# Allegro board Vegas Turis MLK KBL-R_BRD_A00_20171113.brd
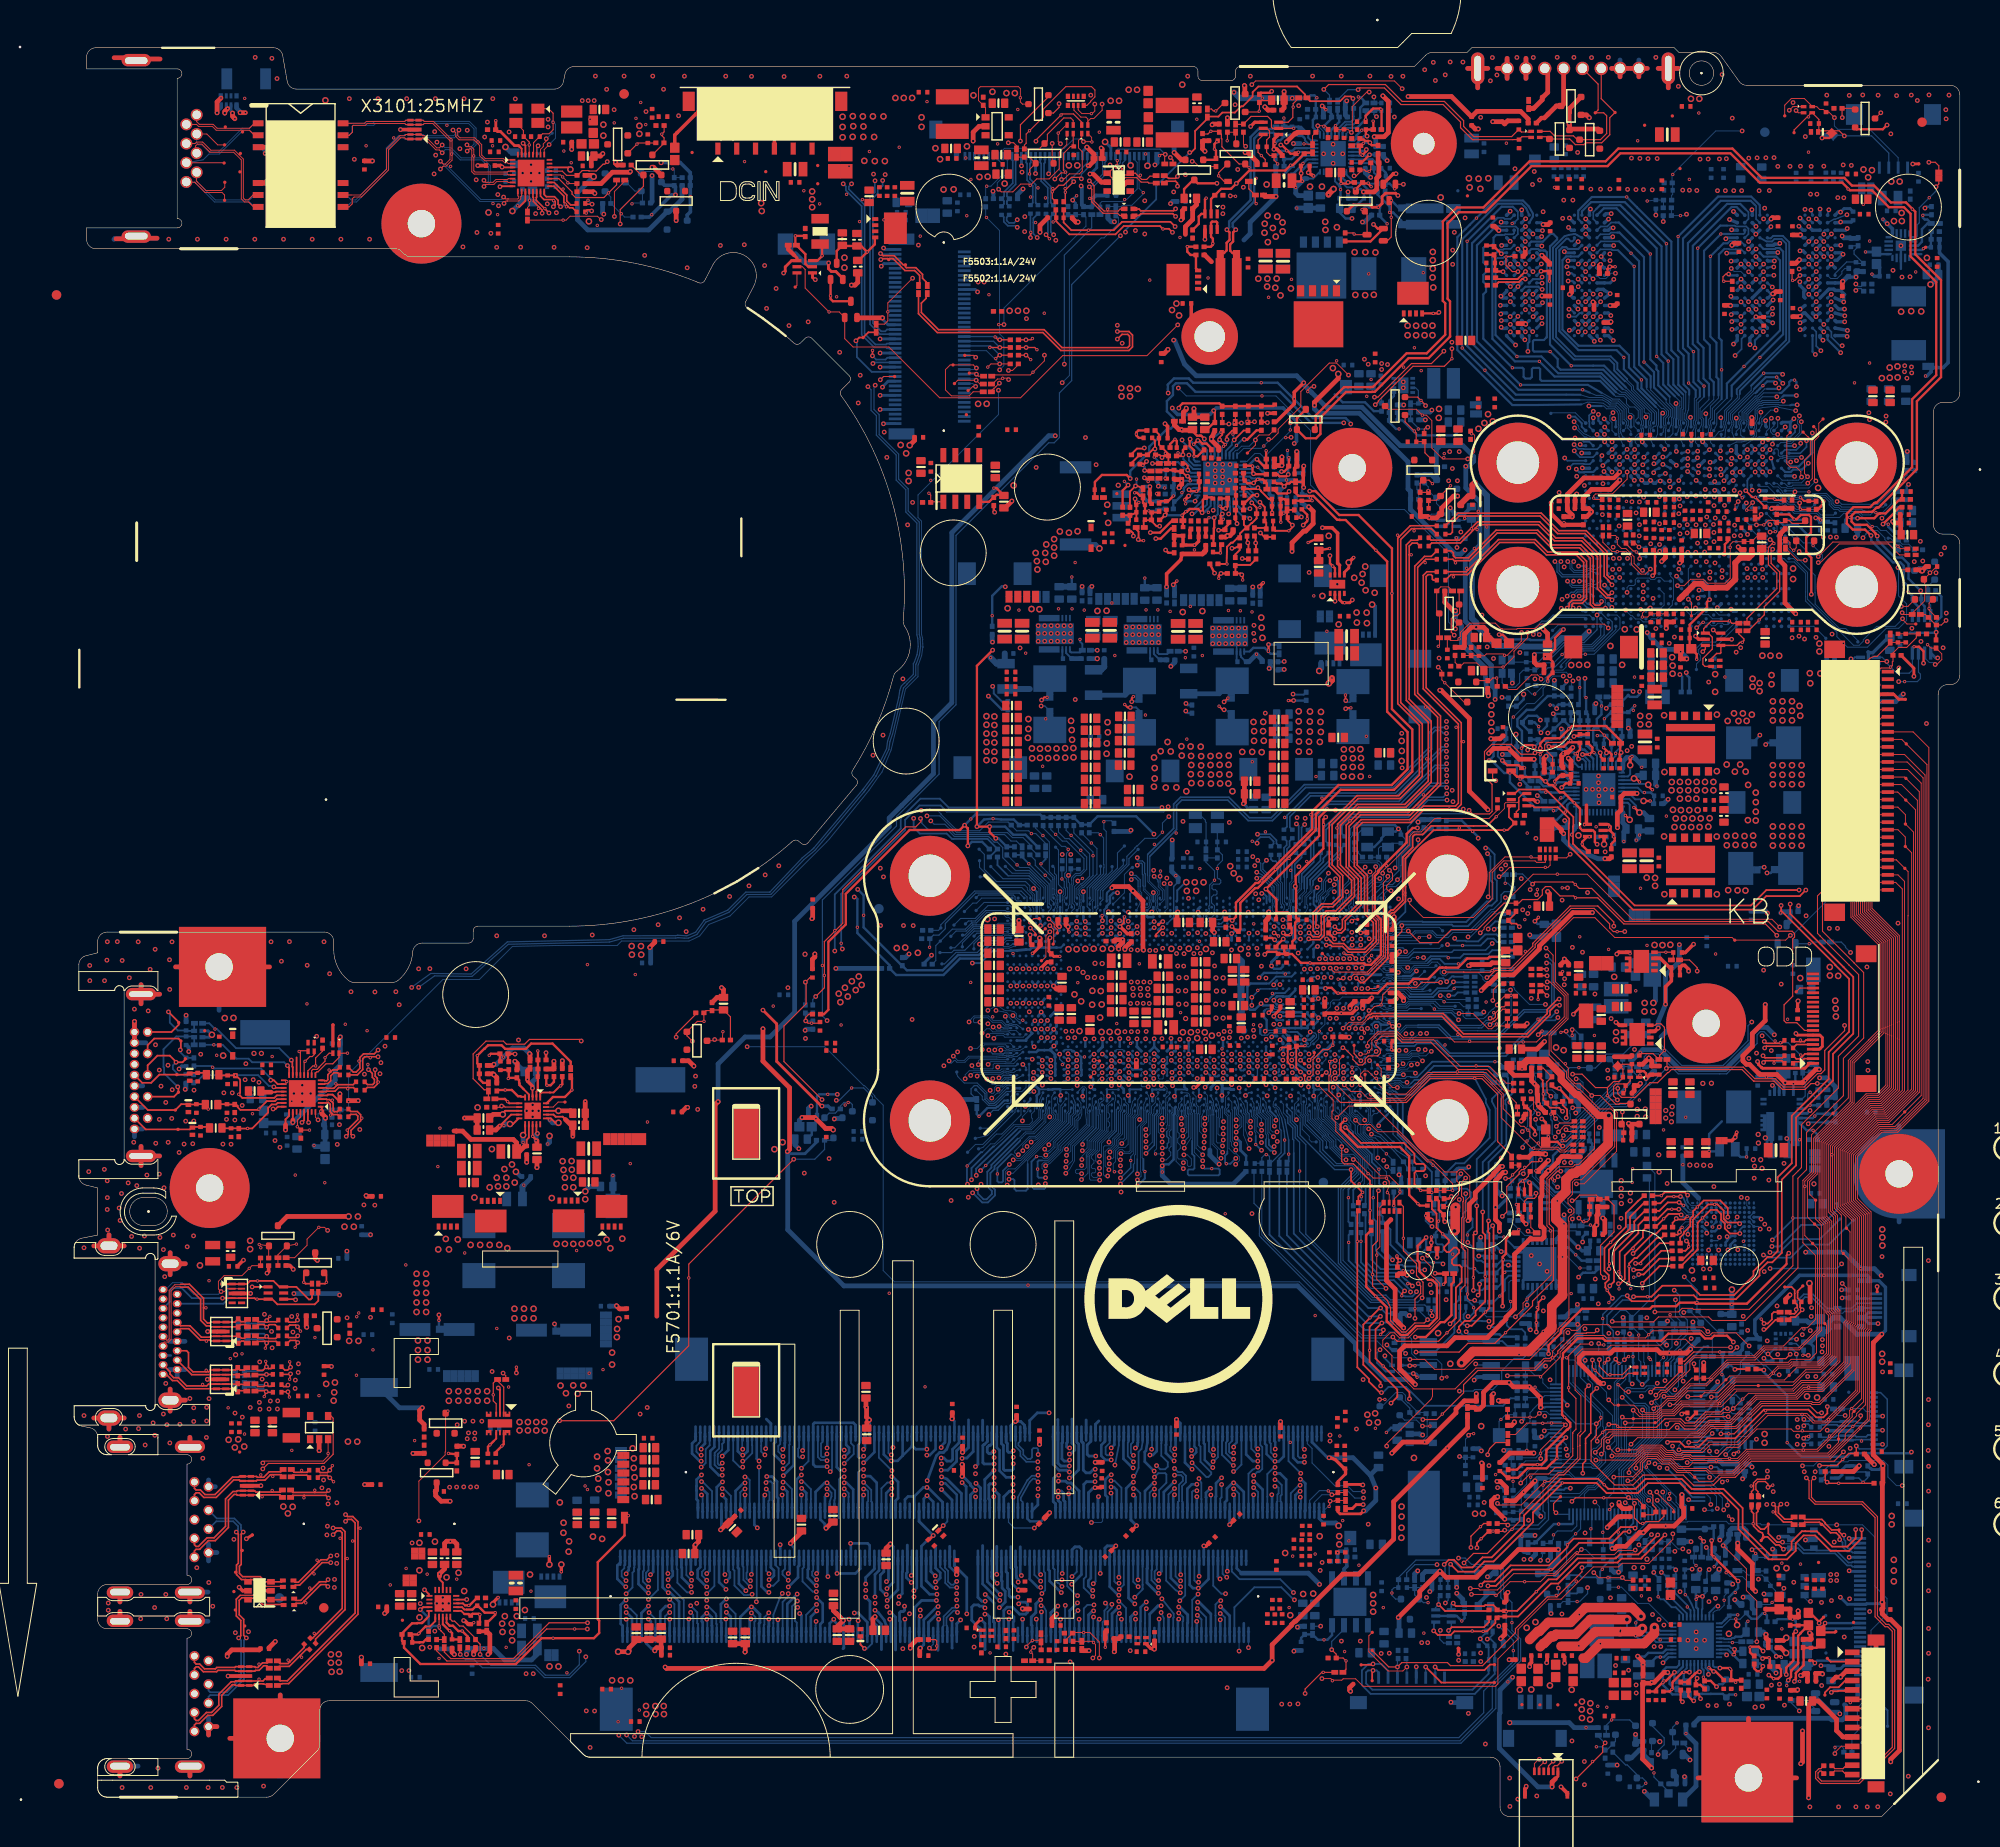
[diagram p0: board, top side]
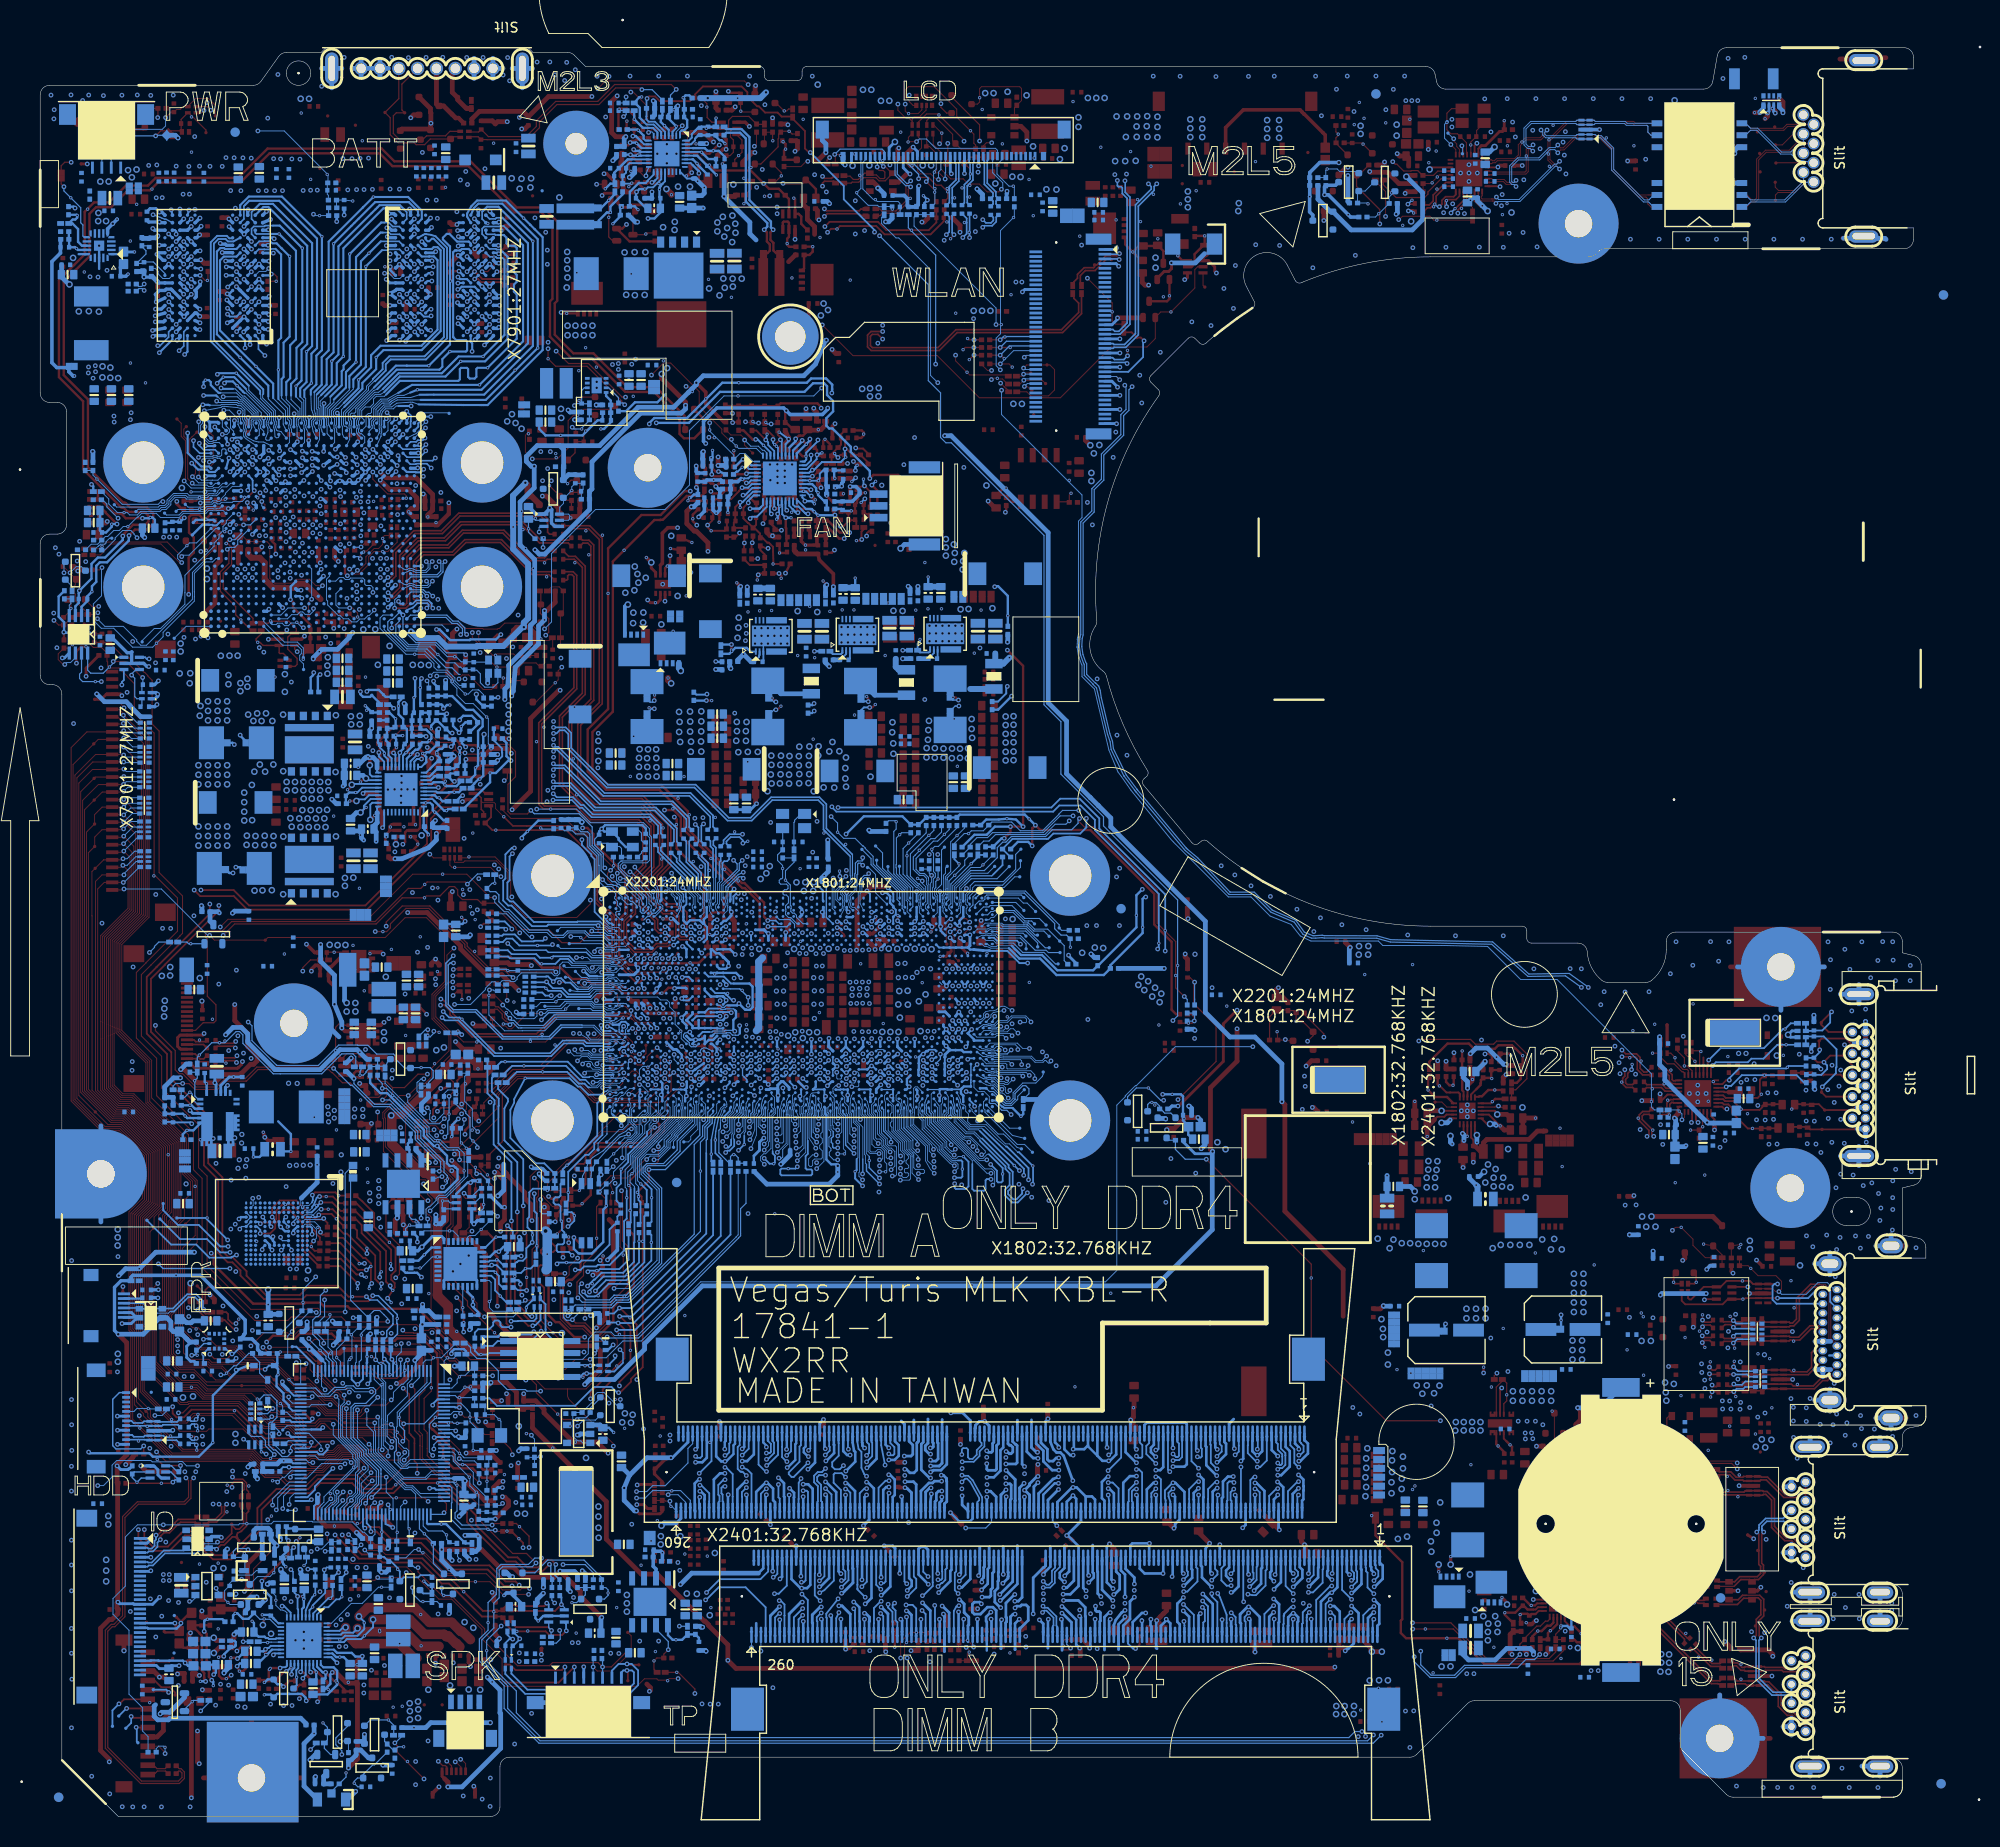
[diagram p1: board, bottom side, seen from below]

Outline 200.35 x 188 mm; copper layers: TOP, L2, L3, L4, L5GND, BOTTOM. Coordinates in mm from the lower left corner of the outline.

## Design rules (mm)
constraint set DEFAULT: min track width 0.127, pair gap 0.102
net group AUDIO_12MIL: nets CPVEE V3D3_STB
net group CL_CLK: nets CL_CLK CL_CLK_R
net group CL_DATA: nets CL_DATA CL_DATA_R
net group CL_RST#: nets CL_RST# CL_RST#_R
net group CPU_DP1_CTRL_CLK: nets CPU_DP1_CTRL_CLK DDC_CLK_HDMI
net group CPU_DP1_CTRL_DATA: nets CPU_DP1_CTRL_DATA DDC_DATA_HDMI
net group DDR4_A_ODT40-MW: nets M_A_DIMA_ODT0 M_A_DIMA_ODT1
net group DDR4_B_ODT40-MW: nets M_B_DIMB_ODT0 M_B_DIMB_ODT1
net group EDP_AUX_CPU-DIFF202: nets EDP_AUX_CPU_N EDP_AUX_CPU_P
net group EDP_TX_CON_N0: nets EDP_TX_CON_N0 EDP_TX_CPU_N0
net group EDP_TX_CON_N1: nets EDP_TX_CON_N1 EDP_TX_CPU_N1
net group EDP_TX_CON_P0: nets EDP_TX_CON_P0 EDP_TX_CPU_P0
net group EDP_TX_CON_P1: nets EDP_TX_CON_P1 EDP_TX_CPU_P1
net group EMMC_CLK: nets EMMC_CLK EMMC_CLK_R
net group EMMC_CMD: nets EMMC_CMD EMMC_CMD_R
net group EMMC_D0: nets EMMC_D0 EMMC_D0_R
net group EMMC_D1: nets EMMC_D1 EMMC_D1_R
net group EMMC_D2: nets EMMC_D2 EMMC_D2_R
net group EMMC_D3: nets EMMC_D3 EMMC_D3_R
net group EMMC_D4: nets EMMC_D4 EMMC_D4_R
net group EMMC_D5: nets EMMC_D5 EMMC_D5_R
net group EMMC_D6: nets EMMC_D6 EMMC_D6_R
net group EMMC_D7: nets EMMC_D7 EMMC_D7_R
net group EMMC_RCLK: nets EMMC_RCLK EMMC_RCLK_R
net group ESPI_CLK: nets ESPI_CLK ESPI_CLK_CPU
net group ESPI_CS#: nets ESPI_CS# ESPI_CS#_CPU
net group ESPI_IO0: nets ESPI_IO0 ESPI_IO0_CPU
net group ESPI_IO1: nets ESPI_IO1 ESPI_IO1_CPU
net group ESPI_IO2: nets ESPI_IO2 ESPI_IO2_CPU
net group ESPI_IO3: nets ESPI_IO3 ESPI_IO3_CPU
net group ESPI_RESET#: nets ESPI_RESET# ESPI_RESET#_CPU
net group FAN_TACH: nets FAN1_TACH FAN_TACH1
net group FBA_VREF: nets MVREFDA MVREFSA
net group GPU_THERMAL-DIFF220: nets GPU_DMINUS GPU_DPLUS
net group HDA_CODEC_SDIN0: nets HDA_CODEC_SDIN0 HDA_SDIN0
net group HDA_CODEC_SYNC: nets HDA_CODEC_SYNC HDA_SYNC
net group I2C0_SCL_TCH_PAD: nets I2C0_SCL_TCH_PAD I2C1_SCL_R
net group I2C0_SDA_TCH_PAD: nets I2C0_SDA_TCH_PAD I2C1_SDA_R
net group LPC-MW: nets CLKRUN#_R PWR_SECLET
net group M_A_CLK0-DIFF184: nets M_A_CLK0 M_A_CLK#0
net group M_A_CLK1-DIFF185: nets M_A_CLK1 M_A_CLK#1
net group M_A_DQS0-DIFF188: nets M_A_DQS_DN0 M_A_DQS_DP0
net group M_A_DQS1-DIFF188: nets M_A_DQS_DN1 M_A_DQS_DP1
net group M_A_DQS2-DIFF188: nets M_A_DQS_DN2 M_A_DQS_DP2
net group M_A_DQS3-DIFF188: nets M_A_DQS_DN3 M_A_DQS_DP3
net group M_A_DQS4-DIFF188: nets M_A_DQS_DN4 M_A_DQS_DP4
net group M_A_DQS5-DIFF188: nets M_A_DQS_DN5 M_A_DQS_DP5
net group M_A_DQS6-DIFF188: nets M_A_DQS_DN6 M_A_DQS_DP6
net group M_A_DQS7-DIFF188: nets M_A_DQS_DN7 M_A_DQS_DP7
net group M_B_CLK0-DIFF186: nets M_B_CLK0 M_B_CLK#0
net group M_B_CLK1-DIFF187: nets M_B_CLK1 M_B_CLK#1
net group M_B_DQS0-DIFF188: nets M_B_DQS_DN0 M_B_DQS_DP0
net group M_B_DQS1-DIFF188: nets M_B_DQS_DN1 M_B_DQS_DP1
net group M_B_DQS2-DIFF188: nets M_B_DQS_DN2 M_B_DQS_DP2
net group M_B_DQS3-DIFF188: nets M_B_DQS_DN3 M_B_DQS_DP3
net group M_B_DQS4-DIFF188: nets M_B_DQS_DN4 M_B_DQS_DP4
net group M_B_DQS5-DIFF188: nets M_B_DQS_DN5 M_B_DQS_DP5
net group M_B_DQS6-DIFF188: nets M_B_DQS_DN6 M_B_DQS_DP6
net group M_B_DQS7-DIFF188: nets M_B_DQS_DN7 M_B_DQS_DP7
net group MEM_SMBCLK: nets MEM_SMBCLK PCH_SMBCLK
net group MEM_SMBDATA: nets MEM_SMBDATA PCH_SMBDATA
net group NCT7718-DIFF1: nets NCT7718_DXN NCT7718_DXP
net group PBAT_CHG_SMBCLK: nets PBAT_CHG_SMBCLK PBAT_SMBCLK1
net group PBAT_CHG_SMBDAT: nets PBAT_CHG_SMBDAT PBAT_SMBDAT1
net group PCH_DPC_AUX-DIFF: nets PCH_DPC_AUXN PCH_DPC_AUXP
net group PCH_DPC_AUX_U-DIFF: nets PCH_DPC_AUXN_U PCH_DPC_AUXP_U
net group PCH_DPC_N0: nets PCH_DPC_N0 PCH_DPC_N0_U
net group PCH_DPC_N1: nets PCH_DPC_N1 PCH_DPC_N1_U
net group PCH_DPC_P0: nets PCH_DPC_P0 PCH_DPC_P0_U
net group PCH_DPC_P1: nets PCH_DPC_P1 PCH_DPC_P1_U
net group PCIE_CLK_XDP-DIFF1: nets PCIE_CLK_XDP_N PCIE_CLK_XDP_P
net group PCIE_RCOMP-DIFF: nets PCIE_RCOMPN PCIE_RCOMPP
net group PCIE_RX_CON_N5: nets PCIE_RX_CON_N5 PCIE_RX_CPU_N5
net group PCIE_RX_CON_P5: nets PCIE_RX_CON_P5 PCIE_RX_CPU_P5
net group PCIE_RX_CPU6-DIFF192: nets PCIE_RX_CPU_N6 PCIE_RX_CPU_P6
net group PCIE_TX_CON_N5: nets PCIE_TX_CON_N5 PCIE_TX_CPU_N5
net group PCIE_TX_CON_N6: nets PCIE_TX_CON_N6 PCIE_TX_CPU_N6
net group PCIE_TX_CON_P5: nets PCIE_TX_CON_P5 PCIE_TX_CPU_P5
net group PCIE_TX_CON_P6: nets PCIE_TX_CON_P6 PCIE_TX_CPU_P6
net group PEG_CLK_CPU1-DIFF221: nets PEG_CLK1_CPU PEG_CLK1_CPU#
net group PEG_CLK_CPU2-DIFF198: nets PEG_CLK2_CPU PEG_CLK2_CPU#
net group PEG_CLK_GPU-DIFF200: nets PEG_CLK_CPU PEG_CLK_CPU#
net group PEG_RX_CPU_N0: nets PEG_RX_CPU_N0 PEG_RX_GPU_N0
net group PEG_RX_CPU_N1: nets PEG_RX_CPU_N1 PEG_RX_GPU_N1
net group PEG_RX_CPU_N2: nets PEG_RX_CPU_N2 PEG_RX_GPU_N2
net group PEG_RX_CPU_N3: nets PEG_RX_CPU_N3 PEG_RX_GPU_N3
net group PEG_RX_CPU_P0: nets PEG_RX_CPU_P0 PEG_RX_GPU_P0
net group PEG_RX_CPU_P1: nets PEG_RX_CPU_P1 PEG_RX_GPU_P1
net group PEG_RX_CPU_P2: nets PEG_RX_CPU_P2 PEG_RX_GPU_P2
net group PEG_RX_CPU_P3: nets PEG_RX_CPU_P3 PEG_RX_GPU_P3
net group PEG_TX_CPU_N0: nets PEG_TX_CPU_N0 PEG_TX_GPU_N0
net group PEG_TX_CPU_N1: nets PEG_TX_CPU_N1 PEG_TX_GPU_N1
net group PEG_TX_CPU_N2: nets PEG_TX_CPU_N2 PEG_TX_GPU_N2
net group PEG_TX_CPU_N3: nets PEG_TX_CPU_N3 PEG_TX_GPU_N3
net group PEG_TX_CPU_P0: nets PEG_TX_CPU_P0 PEG_TX_GPU_P0
net group PEG_TX_CPU_P1: nets PEG_TX_CPU_P1 PEG_TX_GPU_P1
net group PEG_TX_CPU_P2: nets PEG_TX_CPU_P2 PEG_TX_GPU_P2
net group PEG_TX_CPU_P3: nets PEG_TX_CPU_P3 PEG_TX_GPU_P3
net group POWER_320M_POWER: nets PQ4416_1 PWR_CHG_DCIN_D
net group PWR_25_10: nets PWR_VGA_CORE_PH1 PWR_VGA_CORE_PH2
net group SATA_RX_CON_N1: nets SATA_RX_CON_N1 SATA_RX_CPU_N1
net group SATA_RX_CON_P1: nets SATA_RX_CON_P1 SATA_RX_CPU_P1
net group SATA_TX_CON_N1: nets SATA_TX_CON_N1 SATA_TX_CPU_N1
net group SATA_TX_CON_P1: nets SATA_TX_CON_P1 SATA_TX_CPU_P1
net group SENSE_CHG_AC-DIFF: nets PWR_CHG_ACN PWR_CHG_ACP
net group SENSE_CHG_PG-DIFF1: nets PG_1 PG_2
net group SENSE_CHG_SR-DIFF: nets PWR_CHG_SRN PWR_CHG_SRP
net group SIGNAL_V_F_8_OHM-MW: nets CFG3 XDP_DBRESET#
net group SIGNAL_V_F_16.5_SVID-MWS: nets VR_SVID_CLK VR_SVID_DATA
net group SPI-MW: nets SIO_RCIN# SPI_IRQ#_TPM2
net group SPI_CS_CPU_N0: nets SPI_CS_CPU_N0 SPI_CS_ROM_N0
net group SUSCLK_R: nets SUS_CLK SUSCLK_R
net group UART_2_CRXD_DTXD: nets UART_2_CRXD_DTXD UART_2_CRXD_DTXD_CON
net group UART_2_CTXD_DRXD: nets UART_2_CTXD_DRXD UART_2_CTXD_DRXD_CON
net group USB30_RX_CPU_N1: nets USB3_PRX_CTX_N1_C USB30_RX_CPU_N1
net group USB30_RX_CPU_N2: nets USB3_PRX_CTX_N2_C USB30_RX_CPU_N2
net group USB30_RX_CPU_P1: nets USB3_PRX_CTX_P1_C USB30_RX_CPU_P1
net group USB30_RX_CPU_P2: nets USB3_PRX_CTX_P2_C USB30_RX_CPU_P2
net group USB_CAMERA_PN4: nets USB_CAMERA_PN4 USB_CPU_PN4
net group USB_CAMERA_PP4: nets USB_CAMERA_PP4 USB_CPU_PP4
net group USB_CON_PN6: nets USB_CON_PN6 USB_CPU_PN6
net group USB_CON_PN7: nets USB_CON_PN7 USB_CPU_PN7
net group USB_CON_PP6: nets USB_CON_PP6 USB_CPU_PP6
net group USB_CON_PP7: nets USB_CON_PP7 USB_CPU_PP7
net group USB_CPU_PN0: nets USB_CPU_PN0 USB_PN0_C
net group USB_CPU_PN1: nets USB_CPU_PN1 USB_PN1_C
net group USB_CPU_PN2: nets USB_CPU_PN2 USB_PN2_C
net group USB_CPU_PN5: nets USB_CPU_PN5 USB_PN5_C
net group USB_CPU_PN8: nets USB_CPU_PN8 USB_PN8_C
net group USB_CPU_PP0: nets USB_CPU_PP0 USB_PP0_C
net group USB_CPU_PP1: nets USB_CPU_PP1 USB_PP1_C
net group USB_CPU_PP2: nets USB_CPU_PP2 USB_PP2_C
net group USB_CPU_PP5: nets USB_CPU_PP5 USB_PP5_C
net group USB_CPU_PP8: nets USB_CPU_PP8 USB_PP8_C
net group VCCGT_ISEN1-DIFF1: nets PWR_VCCGT_ISEN1 PWR_VCCGT_ISEN2
net group VCCGT_ISUM-DIFF1: nets PWR_VCCGT_ISUMN PWR_VCCGT_ISUMP
net group VCCGT_ISUM_GA-DIFF1: nets PWR_VCCGT_ISUMN_GA PWR_VCCGT_ISUMP_GA
net group VCCGT_ISUM_GB-DIFF1: nets PWR_VCCGT_ISUMN_GB PWR_VCCGT_ISUMP_GB
net group VCCSA_ISUM-DIFF1: nets PWR_VCCSA_ISUMN PWR_VCCSA_ISUMP
net group VCCSA_ISUM_R-DIFF1: nets PWR_VCCSA_ISUMN_R PWR_VCCSA_ISUMP_R
net group VCORE_ISUM-DIFF1: nets PWR_VCORE_ISUMN PWR_VCORE_ISUMP
net group VCORE_ISUM_G-DIFF1: nets PWR_VCORE_ISUMN_G PWR_VCORE_ISUMP_G
net group VRAM_VREFC: nets VREFC_A0 VREFC_A1
net group VRAM_WCAK0_1-DIFF1: nets WCKA0_1 WCKA0B_1
net group VRAM_WCAK1_0-DIFF1: nets WCKA1_0 WCKA1B_0
net group XDP_TCLK-MWS: nets XDP_TCK_JTAGX XDP_TCLK
net group XTAL24_IN: nets XTAL24_IN XTAL24_IN_R
net group AUDIO_BEEP_10MIL: nets AUD_HP1_JACK_L AUD_HP1_JACK_L1 AUD_HP1_JACK_R AUD_HP1_JACK_R1 AUD_PC_BEEP AUD_PC_BEEP_C AUD_PORTA_L_R_B AUD_PORTA_R_R_B AUD_SENSE AUD_SENSE_A AUD_VREF BEEP CBN CBP HDA_SPKR_R JACK_PLUG KBC_BEEP_R LINE1-L_C LINE1-L_R LINE1_L LINE1_R LINE1_VREFO LINE1_VREFO_D1 LINE1_VREFO_D2 MIC2_VREFO SPKR
net group CARD_12MIL: nets RSET
net group CFG_50-MW: nets CFG0 CFG1 CFG2 CFG4 CFG5 CFG6 CFG7 CFG8 CFG9 CFG10 CFG11 CFG12 CFG13 CFG14 CFG15 CFG16 CFG17 CFG18 CFG19
net group CLK_50-MW: nets CLKTESTA CLKTESTA_C CLKTESTB CLKTESTB_C ESPI_CLK_CON WLAN_CLKREQ_WLAN#
net group COMP_20MIL: nets CFG_RCOMP CPU_POPIRCOMP CSI2_COMP EDP_COMP EDRAM_OPIO_RCOMP EOPIO_RCOMP PCH_POPIRCOMP SD_RCOMP USBCOMP XCLK_BIASREF
net group CPU_50-MW: nets CMP_VOUT1_R H_PROCHOT# H_PROCHOT#_EC H_PROCHOT#_R PROCHOT
net group CRT_50-MW: nets CRT_B CRT_G CRT_R DP_CRT_B DP_CRT_G DP_CRT_R
net group CRT_SYNC_50-MW: nets CRT_HSYNC_CON CRT_VSYNC_CON DP_CRT_HSYNC_CON DP_CRT_VSYNC_CON
net group DDR4_A_CMD_40-MW: nets M_A_A0 M_A_A1 M_A_A2 M_A_A3 M_A_A4 M_A_A5 M_A_A6 M_A_A7 M_A_A8 M_A_A9 M_A_A10 M_A_A11 M_A_A12 M_A_A13 M_A_A14 M_A_A15 M_A_A16 M_A_ACT_N M_A_ALERT_N M_A_PARITY
net group DDR4_A_DATA_00_50-MW: nets M_A_DQ0 M_A_DQ1 M_A_DQ2 M_A_DQ3 M_A_DQ4 M_A_DQ5 M_A_DQ6 M_A_DQ7
net group DDR4_A_DATA_01_50-MW: nets M_A_DQ8 M_A_DQ9 M_A_DQ10 M_A_DQ11 M_A_DQ12 M_A_DQ13 M_A_DQ14 M_A_DQ15
net group DDR4_A_DATA_02_50-MW: nets M_A_DQ16 M_A_DQ17 M_A_DQ18 M_A_DQ19 M_A_DQ20 M_A_DQ21 M_A_DQ22 M_A_DQ23
net group DDR4_A_DATA_03_50-MW: nets M_A_DQ24 M_A_DQ25 M_A_DQ26 M_A_DQ27 M_A_DQ28 M_A_DQ29 M_A_DQ30 M_A_DQ31
net group DDR4_A_DATA_04_50-MW: nets M_A_DQ32 M_A_DQ33 M_A_DQ34 M_A_DQ35 M_A_DQ36 M_A_DQ37 M_A_DQ38 M_A_DQ39
net group DDR4_A_DATA_05_50-MW: nets M_A_DQ40 M_A_DQ41 M_A_DQ42 M_A_DQ43 M_A_DQ44 M_A_DQ45 M_A_DQ46 M_A_DQ47
net group DDR4_A_DATA_06_50-MW: nets M_A_DQ48 M_A_DQ49 M_A_DQ50 M_A_DQ51 M_A_DQ52 M_A_DQ53 M_A_DQ54 M_A_DQ55
net group DDR4_A_DATA_07_50-MW: nets M_A_DQ56 M_A_DQ57 M_A_DQ58 M_A_DQ59 M_A_DQ60 M_A_DQ61 M_A_DQ62 M_A_DQ63
net group DDR4_B_CMD_40-MW: nets M_B_A0 M_B_A1 M_B_A2 M_B_A3 M_B_A4 M_B_A5 M_B_A6 M_B_A7 M_B_A8 M_B_A9 M_B_A10 M_B_A11 M_B_A12 M_B_A13 M_B_A14 M_B_A15 M_B_A16 M_B_ACT_N M_B_ALERT_N M_B_PARITY
net group DDR4_B_DATA_00_50-MW: nets M_B_DQ0 M_B_DQ1 M_B_DQ2 M_B_DQ3 M_B_DQ4 M_B_DQ5 M_B_DQ6 M_B_DQ7
net group DDR4_B_DATA_01_50-MW: nets M_B_DQ8 M_B_DQ9 M_B_DQ10 M_B_DQ11 M_B_DQ12 M_B_DQ13 M_B_DQ14 M_B_DQ15
net group DDR4_B_DATA_02_50-MW: nets M_B_DQ16 M_B_DQ17 M_B_DQ18 M_B_DQ19 M_B_DQ20 M_B_DQ21 M_B_DQ22 M_B_DQ23
net group DDR4_B_DATA_03_50-MW: nets M_B_DQ24 M_B_DQ25 M_B_DQ26 M_B_DQ27 M_B_DQ28 M_B_DQ29 M_B_DQ30 M_B_DQ31
net group DDR4_B_DATA_04_50-MW: nets M_B_DQ32 M_B_DQ33 M_B_DQ34 M_B_DQ35 M_B_DQ36 M_B_DQ37 M_B_DQ38 M_B_DQ39
net group DDR4_B_DATA_05_50-MW: nets M_B_DQ40 M_B_DQ41 M_B_DQ42 M_B_DQ43 M_B_DQ44 M_B_DQ45 M_B_DQ46 M_B_DQ47
net group DDR4_B_DATA_06_50-MW: nets M_B_DQ48 M_B_DQ49 M_B_DQ50 M_B_DQ51 M_B_DQ52 M_B_DQ53 M_B_DQ54 M_B_DQ55
net group DDR4_B_DATA_07_50-MW: nets M_B_DQ56 M_B_DQ57 M_B_DQ58 M_B_DQ59 M_B_DQ60 M_B_DQ61 M_B_DQ62 M_B_DQ63
net group DDR4_BA_BG_40-MW: nets M_A_BA0 M_A_BA1 M_A_BG0 M_A_BG1 M_B_BA0 M_B_BA1 M_B_BG0 M_B_BG1
net group DDR4_CKE_40-MW: nets M_A_CKE0 M_A_CKE1 M_A_CS#0 M_A_CS#1 M_B_CKE0 M_B_CKE1 M_B_CS#0 M_B_CS#1
net group DDR4_RST: nets DDR4_DRAMRST#
net group DDR4_VREF_40: nets V_SM_VREF_CNTA
net group EMMC_S10: nets EMMC_E9 EMMC_E10 EMMC_F10 EMMC_K10 EMMC_RESET#
net group ERROR: nets N171297876 N171299768 N171301627 N171301632 N171301637 N171301642 N171378840 N171586817 N171586827 N171586837 N172436911
net group ESPI_50-MW: nets ESPI_ALERT# ESPI_CS#_CON ESPI_IO0_CON ESPI_IO1_CON ESPI_IO2_CON ESPI_IO3_CON ESPI_RESET#_CON
net group FFS: nets FALL_INT2 FFS_INT2 FFS_INT2_Q HDD_FALL_INT
net group GND: nets MIC_GND
net group HDA_BITCLK: nets HDA_BITCLK HDA_BITCLK_CODEC_R HDA_CODEC_BITCLK
net group HDA_CODEC_SDOUT: nets HDA_CODEC_SDOUT HDA_SDOUT HDA_SDOUT_CODEC_R
net group HDMI_CLK: nets HDMI_CLK HDMI_CLK_R HDMI_CLK_R_C
net group HDMI_CLK#: nets HDMI_CLK# HDMI_CLK#_R HDMI_CLK#_R_C
net group HDMI_DATA0: nets HDMI_DATA0 HDMI_DATA0_R HDMI_DATA0_R_C
net group HDMI_DATA0#: nets HDMI_DATA0# HDMI_DATA0#_R HDMI_DATA0#_R_C
net group HDMI_DATA1: nets HDMI_DATA1 HDMI_DATA1_R HDMI_DATA1_R_C
net group HDMI_DATA1#: nets HDMI_DATA1# HDMI_DATA1#_R HDMI_DATA1#_R_C
net group HDMI_DATA2: nets HDMI_DATA2 HDMI_DATA2_R HDMI_DATA2_R_C
net group HDMI_DATA2#: nets HDMI_DATA2# HDMI_DATA2#_R HDMI_DATA2#_R_C
net group JTAG-MW: nets PCH_JTAG_TCK PCH_JTAG_TDI PCH_JTAG_TDO PCH_JTAG_TMS
net group KBC: nets KSI0 KSI1 KSI2 KSI3 KSI4 KSI5 KSI6 KSI7 KSO0 KSO1 KSO2 KSO3 KSO4 KSO5 KSO6 KSO7 KSO8 KSO9 KSO10 KSO11 KSO12 KSO13 KSO14 KSO15 KSO16
net group LAN_MDI0N: nets MDO0-
net group LAN_MDI0P: nets MDO0+
net group LAN_MDI1N: nets MDO1-
net group LAN_MDI1P: nets MDO1+
net group LAN_MDI2N: nets MDO2-
net group LAN_MDI2P: nets MDO2+
net group LAN_MDI3N: nets MDO3-
net group LAN_MDI3P: nets MDO3+
net group LCD_BKLT: nets BKLT_CTRL EC_BRIGHTNESS EDP_BKLT_CTRL L_BKLT_CTRL LCD_BRIGHTNESS
net group LED: nets BAT1_LED# BAT2_LED# BATT_WHITE_LED# CAP_LED# CAP_LED#_S CAP_LED_R# CHG_AMBER_LED# SATA_LED#_R
net group LED_20MIL: nets BAT_AMBER BAT_WHITE CAP_LED CAP_LED_Q WHITE_LED_BAT
net group OTHER_4MIL: nets 3.3V_ALW_1 3.3V_RUN_VGA_1 3V_5V_DSW_OK A67_TP A70_TP AC_DIS AC_IN_KBC# AC_PRESENT AD_IA ATI_RST# AUX_ON AV1_TP AV71_TP B71_TP BA1_TP BB70_TP BKLT_IN_EC BLON_OUT_C BLUETOOTH_EN BLUETOOTH_EN_NGFF BOARD_ID BOARD_ID2 BOARD_ID_R BREATH_LED# CLKREQ_PCIE#1 CLKREQ_PCIE#2 CLKREQ_PCIE#3 CLKREQ_PCIE#4 CLKREQ_PCIE#5 CLKREQ_PEG#0 CMP_VIN1 CPU_DP1_HPD CPU_DP2_HPD CRT_PCH_HPD DBC_EN_R DBC_PANEL_EN DDPD_CTRLDATA DGPU_PWROK_EC DRAM_RST DRAM_RST_R DRAM_RST_VGA1 DVSS E51_RX1 E51_RX2 E51_TX1 E51_TXD_R EDP_DISP_UTIL EDP_HPD EDP_HPD_CONN FPR_SCAN# GPD2/LAN_WAKE# GPD9/SLP_WLAN# GPIO16_VGA GPIO_8_ROMSO GPIO_9_ROMSI GPIO_10_ROMSCK GPIO_17_THERMAL_INT GPIO_19_CTF GPIO_22_ROMCS# GPP_B4/CPU_GP3 GPP_B18/GSPI0_MOSI GPP_B23/SML1ALERT# GPP_C2/SMBALERT# GPP_C5/SML0ALERT# GPP_E0/SATAXPCIE0/SATAGP0 GPU_ALERT# GPU_DPRSLP GPU_DPRSLP_R H_CATERR# H_VID3 H_VID4 HDD_DEVSLP_R HDMI_HPD_B HDMI_HPD_E HOST_DEBUG_TX HOST_DEBUG_TX_CON HPD_HDMI_CON HW_ACAV_IN HW_ACAVIN_NB I_ADP ICSP_CLR ICSP_MCLR_R INT_TP# ISOLATE# JET_SVC JET_SVD JTAG_TCK_VGA JTAG_TDI_VGA JTAG_TDO_VGA JTAG_TMS_VGA JTAG_TRST#_VGA KB_LED_PWM KBC_PWRBTN# L_BKLT_EN LAN_CLKREQ_LAN# LANWAKE# LCD_TST LCD_TST_C LCD_TST_R LCDVDD_EN LED0 LED1 LED2 LID_CL_SIO# LID_CLOSE#_C MASK_SATA_LED# ME_FWP MEM_CALRP0 MESO_SVC MESO_SVD MESO_SVT MESO_U1 MESO_U3 MLPS_EN# MODEL_ID MSM# NB_MUTE# NC#AA3 NC_R NC_VSYNC P_SYS PANEL_BKEN_EC PANEL_SIZE_ID PANEL_SIZE_ID_CONN PCH_BATLOW# PCH_THERMTRIP PCH_WAKE# PDB_R PIRQA# PLL_ANALOG_IN PLT_RST#_Q_TPM2 PLT_RST_NGFF# PME# POWER_SW_IN# PQ3802_1 PRIM_PWRGD PROC_SELECT# PROJECT_ID1 PROJECT_ID2 PS_0 PS_1 PS_2 PS_3 PSID_DISABLE#_R_C PWR_5V_VCLK PWR_CHG_ACOK PWRGOOD_TEST PX_EN RESET_OUT# RTC_3P3_EN_D RTC_3P3_EN_G RTC_DET# SA0_CHA_DIM0 SA0_CHB_DIM0 SA1_CHA_DIM0 SA1_CHB_DIM0 SA2_CHA_DIM0 SA2_CHB_DIM0 SERIRQ_TPM SIO_EXT_SCI# SIO_EXT_SMI#_R SIO_EXT_WAKE# SIO_PWRBTN# SIO_SLP_A# SIO_SLP_S5# SKTOCC# SM_INTRUDER# SYSPWR_PRES TESTEN TOUCHPAD_INTR# TP_RESET TP_RS TP_WAKE_KBC# TPM_GPIO0 TPM_GPIO2 TPM_GPIO4 USB_OC1# USB_OC2# USB_POWERSHARE_VBUS_EN USB_PWR_SHR_EN_L# USB_UART_SEL_D9 VCCDSW_EN# VCCDSW_ON VCI_IN1# VCREF0 VGA_RST# VR_RDY VRAM_ID1 VSS_MECH1 VSS_MECH2 VSS_MECH3 WIFI_RF_EN WLAN_DISABLE#1 WLAN_WAKE XO_IN XO_IN2 ZVM#
net group PECI-MW: nets H_PECI_R
net group PLATFORM: nets 0D95V_VGA_EN 0D95V_VGA_EN_R 0D95V_VGA_S0_PG 1D0V_S5_PWRGD 1D8V_EN# 1D8V_EN_R# 1D8V_VGA_EN 1D8V_VGA_EN# 1D8V_VGA_EN_R# 2D5V_PWROK 3V5V_S0_ON 3V_5V_POK 3V_5V_POK# 3V_5V_POK_C ACLIM ALWON BATT_WHITE_LED_R# BLON_OUT BP_D BP_G CAMERA_DET# CAMERA_DET#_R CHG_AMBER_LED_R# EDP_VDD_EN EXT_CLK_IN_CRT EXT_PWR_GATE# FAN2_PWMVOL_LP# GPD11/LANPHYPC GPIO_5_AC_BATT GPP_B22 H_CPUPWRGD H_VCCST_PWRGD H_VCCST_PWRGD_R KBC_PWRBTN#_C LAN_ENABLE_R_C LCD_VCC_TEST_EN LCD_VCC_TEST_EN_R ME_SUS_PWR_ACK_R NB_MODE# PCH_DPWROK PCH_PLTRST# PCH_RSMRST# PCIE_CALR_RX PCIE_CALR_TX PCIE_WAKE# PD4404_A PD4404_K PLT_RST#_LAN PM_LAN_ENABLE PM_LAN_ENABLE_C PM_PCH_PWROK PM_RSMRST# PM_RSMRST#_M POL1/SPI_CEB POL2 PQ4406_2 PQ4406_3 PQ4406_5 PQ4406_6 PQ4409_C PQ4409_E PTP_DIS# PWR_1D0V_EN PWR_1D0V_PG PWR_1D8V_EN PWR_1D8V_POK PWR_1D35V_EN PWR_2D5V_POK PWR_VDDQ_PG PWR_VTT_EN Q502_G Q4009_G RSMRST_PWRGD# RTC_RST# RTCRST_ON RUNPWROK SATA_ODD_DA#_C SATA_ODD_PRSNT# SATA_ODD_PRSNT#_R SIO_SLP_S4# SLP_LAN# SLP_SUS# SM_DRAMRST# SM_PGCNTL SM_PGCNTL_R SPI_CLK_CRT SPI_SI_CRT SPI_SO_CRT SRTC_RST# SUSACK#_R TP_EN# TP_LOCK# TP_ON#_GATE TPM_SELECT TS#_DIMM0_1 TS#_DIMM1_1 USB2_ID USB2_VBUSSENSE USB_EN# USB_PWR_EN# VCCSTG_EN_R VCCSTU_EN_R
net group POWER_10M: nets 1.8V_RUN_FB 3D3V_RTC_SYS 3V5V_CT1 3V5V_CT2 +VCCAMPHYPLL_1P0 +VCCAPLL_1P0 +VCCDSW_1P0 +VCCFUSEPRG +VCCPAZIO +VCCPDSW_3P3 +VCCPRTC_3P3 +VCCST_CPU +VCCSTG +VDDQ_CPU_CLK ACOK_IN BOOST_MON FAN1_DAC_1 FAN1_PWM I_BATT LDO1_CAP LDO2_CAP LDO3_CAP MF_A0 MF_A1 MIC_CAP Q6204_G SEN_A0 SEN_A1 TPM_VDD14 TPM_VSB VCCRTCEXT VREF_CPU ZQ_A0 ZQ_A1
net group POWER_10M_POWER: nets 3V_FEEDBACK AC_DIS_R AC_IN#_G AD+_G_1 AD+_G_2 AD+_R AD_OFF_L AD_OFF_R CCLIM DC_IN_D DPLL_PVDD DPLL_VDDC EN/DEM_VGA MPV18 PQ3809_D PQ8206_3 PR_2 PWR_OPCN PWR_OPCP PWR_VBAT SPV10 SPV18 TOPAZ_OCP VGA_SVC VGA_SVD VGA_SVT VGA_VDD_RUN_FB_H VGA_VDD_RUN_FB_L VGA_VSUM-_1 VSS_AY71
net group POWER_15M: nets 3D3V_TP_S5_R PS_ID PS_ID_R PS_ID_R1 Q6205_Q
net group POWER_20M: nets 1D8V_S0 1D8V_S5_KBC 3D3V_AUX_KBC_R 3D3V_AUX_S5 +3V_1D8V_AVDD +RTC_CELL_VBAT +RTC_VCC +V_VREF_PATH1 CCG4_I2C_INT# EMMC_VDDI MCT0 MCT1 MCT2 MCT3 PBAT_PRES1# PBAT_PRES# RTC_3D3V RTC_AUX_S5 SYS_PRES1#
net group POWER_20M_POWER: nets 3D3V_PWR_2 5V_PWR_2 AVCC33 CPVDD
net group POWER_40M: nets 3D3V_S5_PCH_GEN9
net group POWER_40M_POWER: nets PWR_VDDQ_VTTREF
net group POWER_120MIL: nets PWR_VCORE_VIN PWR_VDDQ_VDDQ PWR_VGA_CORE_VDDIO
net group POWER_2680M_POWER: nets U22_POWER_K52
net group PWR_10_10: nets PWR_1D0V_PFM PWR_1D0V_SS PWR_1D0V_TON PWR_1V35V_ILMT PWR_2D5V_EN PWR_3D3V_CS2 PWR_3D3V_EN2 PWR_5V_CS1 PWR_5V_EN1 PWR_5V_EN1_R PWR_CHG_ACDET PWR_CHG_AMON PWR_CHG_BATGONE PWR_CHG_BMON PWR_CHG_CMSRC PWR_CHG_COMP PWR_CHG_DCIN PWR_CHG_DCIN_R PWR_CHG_FSET PWR_CHG_NTC PWR_CHG_NTC_1 PWR_CHG_PROG PWR_CHG_REGN PWR_CHG_SCL PWR_CHG_SDA PWR_CHG_SRN_R PWR_CHG_SRP_R PWR_VCCGT_COMP PWR_VCCGT_COMP1 PWR_VCCGT_FCCM# PWR_VCCGT_FCCM#_RA PWR_VCCGT_FCCM#_RB PWR_VCCGT_IMON PWR_VCCGT_ISUMN_P_1 PWR_VCCGT_ISUMN_P_2 PWR_VCCGT_ISUMN_RC PWR_VCCGT_ISUMNB PWR_VCCGT_NTC PWR_VCCGT_NTC1 PWR_VCCGT_RTN PWR_VCCSA_COMP PWR_VCCSA_COMP_RC PWR_VCCSA_FCCM PWR_VCCSA_IMON PWR_VCCSA_ISUMN_P_1 PWR_VCCSA_ISUMN_P_2 PWR_VCCSA_ISUMN_RC PWR_VCCSA_ISUMNB PWR_VCCSA_RTN PWR_VCORE_COMP PWR_VCORE_COMP1 PWR_VCORE_FCCM# PWR_VCORE_FCCM#_R PWR_VCORE_IMON PWR_VCORE_ISUMN_P_1 PWR_VCORE_ISUMN_P_2 PWR_VCORE_ISUMN_RC PWR_VCORE_ISUMNA PWR_VCORE_NTC PWR_VCORE_NTC1 PWR_VCORE_PROG1 PWR_VCORE_PROG2 PWR_VCORE_RTN PWR_VCORE_VRHOT# PWR_VDDQ_CS PWR_VDDQ_EN PWR_VDDQ_TON PWR_VDDQ_VID PWR_VGA_CORE_COMP PWR_VGA_CORE_COMP_1 PWR_VGA_CORE_EN_R# PWR_VGA_CORE_ENABLE PWR_VGA_CORE_IMON_NB PWR_VGA_CORE_ISEN1 PWR_VGA_CORE_ISEN2 PWR_VGA_CORE_ISUMN PWR_VGA_CORE_ISUMP PWR_VGA_CORE_NTC PWR_VGA_CORE_NTC_NB PWR_VGA_CORE_PGOOD PWR_VGA_CORE_PWROK PWR_VGA_CORE_RTN PWR_VGA_CORE_SVC PWR_VGA_CORE_SVD PWR_VGA_CORE_SVT PWR_VGA_CORE_VO1 PWR_VGA_CORE_VO2 PWR_VGA_CORE_VR_HOT# PWR_VGA_CORE_VSEN PWR_VGA_CORE_VSUM-
net group PWR_15_20: nets PWR_0D95V_FB PWR_1D0V_VFB PWR_1D0V_VFB_A PWR_1D35V_FB PWR_1D35V_FB_A PWR_2D5V_FB PWR_3D3V_FB2 PWR_3D3V_FB2_R PWR_5V_FB1 PWR_5V_FB1_R PWR_CHG_ASGATE PWR_VCCGT_FB PWR_VCCGT_FB1 PWR_VCCGT_FB2 PWR_VCCGT_FB_RC PWR_VCCSA_FB PWR_VCCSA_FB_RC PWR_VCORE_FB1 PWR_VCORE_FB2 PWR_VCORE_FB_RC PWR_VDDQ_FB PWR_VGA_CORE_FB PWR_VGA_CORE_FB2_R PWR_VGA_CORE_FB_R
net group PWR_20_10: nets PWR_5V_VO1 PWR_VCCGT_VCCDA PWR_VCCGT_VCCDB PWR_VCORE_VCC PWR_VCORE_VCC_R PWR_VDDQ_VDD PWR_VGA_CORE_IMON PWR_VGA_CORE_VDD VDD
net group PWR_25_30: nets PWR_1D0V_BT PWR_1D0V_SNUB PWR_1D35V_BOOT PWR_1D35V_BOOT_A PWR_3D3V_SNUB PWR_3D3V_VBST2 PWR_3D3V_VBST2_1 PWR_5V_SNUB PWR_5V_VBST1 PWR_5V_VBST1_1 PWR_CHG_BTST PWR_CHG_BTST1 PWR_VCCGT_BOOTA_RC PWR_VCCGT_BOOTB_RC PWR_VCCGT_PWMA PWR_VCCGT_PWMB PWR_VCCGT_SNB2 PWR_VCCSA_BST_RC PWR_VCCSA_DRVL PWR_VCCSA_PWM PWR_VCORE_BOOT_RC PWR_VCORE_PWM PWR_VCORE_SNB PWR_VDDQ_BOOT PWR_VDDQ_BOOT_A PWR_VGA_CORE__BOOT1_1 PWR_VGA_CORE__BOOT2_1 PWR_VGA_CORE_BOOT1 PWR_VGA_CORE_BOOT2
net group REF10M: nets VR_CAP
net group SATA_RX_CON_N0: nets SATA_RX_CPU_N0
net group SATA_RX_CON_P0: nets SATA_RX_CPU_P0
net group SATA_TX_CON_N0: nets SATA_TX_CPU_N0
net group SATA_TX_CON_P0: nets SATA_TX_CPU_P0
net group SENSE: nets VCC_SENSE VCCGT_SENSE VCCSA_SENSE VSS_SENSE VSSGT_SENSE VSSSA_SENSE
net group SIGNAL_V_F_4MIL: nets HDD_DEVSLP ITP_PMODE KB_DET# PLT_RST# USB_OC0# USB_OC3# VR_EN
net group SIGNAL_V_F_5MIL: nets 3V_5V_EN ALL_SYS_PWRGD DGPU_HOLD_RST# DGPU_PWR_EN DGPU_PWR_EN_R DGPU_PWROK DGPU_PWROK_R SIO_SLP_S0# SIO_SLP_S3# SYS_PWROK TOUCH_PANEL_INTR#
net group SIGNAL_V_F_14_OHM-MW: nets VR_SVID_ALERT#
net group SIGNAL_V_F_15_OHM-MW: nets H_PECI
net group SM_RCOMP: nets SM_RCOMP_0 SM_RCOMP_1 SM_RCOMP_2
net group SMB_CLK_THM_R: nets SMB_CLK_THM_R SMB_CLK_VGA SMB_CLK_VGA_R SML1_SMBCLK
net group SMB_DATA_THM_R: nets SMB_DATA_THM_R SMB_DATA_VGA SMB_DATA_VGA_R SML1_SMBDATA
net group SMBUS_50-MWS: nets CLK_TP_SIO CPU_DP2_CTRL_CLK CPU_DP2_CTRL_DATA CRT_DDCCLK_CON CRT_DDCCLK_CON_R CRT_DDCDATA_CON CRT_DDCDATA_CON_R DAT_TP_SIO DDC_CLK_PH1 DDC_DATA_PH2 DMIC_CLK DMIC_CLK_EDP DMIC_CLK_R DMIC_DATA DMIC_DATA_EDP DMIC_DATA_R GPU_THM_SMBCLK GPU_THM_SMBDAT I2C0_SCL I2C0_SDA I2C1_SCL I2C1_SDA ICSP_CLK ICSP_CLK_R ICSP_DAT ICSP_DATA_R SML0_SMBCLK SML0_SMBDATA TPCLK_C TPDATA_C
net group SPI_CLK_CPU: nets SPI_CLK_CPU SPI_CLK_ROM SPI_CLK_ROM_R SPI_CLK_ROM_TPM2
net group SPI_CS2#_R_TPM2: nets SPI_CS2#_R_TPM2 SPI_CS_CPU_N2 SPI_CS_ROM_N2
net group SPI_HOLD_CPU: nets SPI_HOLD_CPU SPI_HOLD_ROM SPI_HOLD_ROM_R
net group SPI_SI_CPU: nets SPI_SI_CPU SPI_SI_ROM SPI_SI_ROM_R SPI_SI_ROM_TPM2
net group SPI_SO_CPU: nets SPI_SO_CPU SPI_SO_ROM SPI_SO_ROM_R SPI_SO_ROM_TPM2
net group SPI_WP_CPU: nets SPI_WP_CPU SPI_WP_ROM SPI_WP_ROM_R
net group SVID-MW: nets H_CPU_SVIDALRT# H_CPU_SVIDCLK H_CPU_SVIDDAT PWR_VCORE_ALERT# PWR_VCORE_SCLK PWR_VCORE_SDIO
net group T8-MW: nets CMP_VIN0 CMP_VIN0_R CMP_VOUT0 VD_IN1_C
net group TESTPD_4MIL: nets CPU_A16_TP CPU_D3_TP CPU_D4_TP CPU_D5_TP CPU_D6_TP RSVD_F65 RSVD_G65 RSVD_TP_AW70 RSVD_TP_AW71 RSVD_TP_BA68 RSVD_TP_BA70 TP1_AY4 TP2_BB3
net group THERM_10M-MS: nets FON#
net group THERM_SHUTDOWN: nets GPU_PWR_LEVEL GPU_PWR_LEVEL_R GPU_T_CRIT# GPU_T_CRIT_R# PURE_HW_SHUTDOWN# THERM_SYS_SHDN#
net group UART_MW-MW: nets LPSS_UART2_CTS# UART0_CTS# UART0_RTS# UART0_TXD UART1_CTS# UART1_RXD
net group USB30_TX_CPU_N1: nets USB3_PTX_CRX_N1_C USB3_PTX_CRX_N1_R USB30_TX_CPU_N1
net group USB30_TX_CPU_N2: nets USB3_PTX_CRX_N2_C USB3_PTX_CRX_N2_R USB30_TX_CPU_N2
net group USB30_TX_CPU_P1: nets USB3_PTX_CRX_P1_C USB3_PTX_CRX_P1_R USB30_TX_CPU_P1
net group USB30_TX_CPU_P2: nets USB3_PTX_CRX_P2_C USB3_PTX_CRX_P2_R USB30_TX_CPU_P2
net group VRAM_DBI: nets DDBIA0_2 DDBIA0_3 DDBIA1_0
net group VRAM_DQA-MWS: nets DQA0_16 DQA0_17 DQA0_18 DQA0_19 DQA0_20 DQA0_21 DQA0_22 DQA0_23 DQA0_24 DQA0_25 DQA0_26 DQA0_27 DQA0_28 DQA0_29 DQA0_30 DQA0_31 DQA1_0 DQA1_1 DQA1_2 DQA1_3 DQA1_4 DQA1_5 DQA1_6 DQA1_7
net group VRAM_EDC: nets EDCA0_2 EDCA0_3 EDCA1_0
net group XDP-MW: nets XDP_PRDY# XDP_PREQ# XDP_TDI XDP_TDO_CPU XDP_TMS XDP_TRST#
net group XDP_BPM-MW: nets XDP_BPM0 XDP_BPM1 XDP_BPM2 XDP_BPM3
net group XTAL24_IN_U42: nets XTAL24_IN_U42
net group XTAL24_OUT_R_U42: nets XTAL24_OUT_U42
net group XTAL-MW: nets LANXIN LANXOUT MEC_XTAL1_R MEC_XTAL2 RTC_X1 RTC_X2 XTAL24_OUT XTAL_KBC_2 XTL_27M_X1_VGA XTL_27M_X2_VGA

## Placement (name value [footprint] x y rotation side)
AFTP2501  AFTE14P-GP  [AFTE14P-75]  34.88 20.86 0 top
AFTP2502  AFTE14P-GP  [AFTE14P-75]  36.71 42.57 0 top
AFTP2601  AFTE14P-GP  [AFTE14P-75]  110.79 140.6 0 top
AFTP2602  AFTE14P-GP  [AFTE14P-75]  109.52 138.5 0 top
AFTP2603  AFTE14P-GP  [AFTE14P-75]  111.65 135.1 0 top
AFTP2901  AFTE14P-GP  [AFTE14P-75]  153.82 11.89 0 top
AFTP2902  AFTE14P-GP  [AFTE14P-75]  155.73 11.86 0 top
AFTP2903  AFTE14P-GP  [AFTE14P-75]  157.64 11.86 0 top
AFTP2904  AFTE14P-GP  [AFTE14P-75]  159.54 11.86 0 top
AFTP3201  AFTE14P-GP  [AFTE14P-75]  16.01 173.7 0 top
AFTP3202  AFTE14P-GP  [AFTE14P-75]  15.93 175.74 0 top
AFTP3203  AFTE14P-GP  [AFTE14P-75]  17.66 176.76 0 top
AFTP3204  AFTE14P-GP  [AFTE14P-75]  15.98 171.78 0 top
AFTP3205  AFTE14P-GP  [AFTE14P-75]  17.61 174.8 0 top
AFTP3206  AFTE14P-GP  [AFTE14P-75]  16.06 179.58 0 top
AFTP3207  AFTE14P-GP  [AFTE14P-75]  17.89 179.05 0 top
AFTP3208  AFTE14P-GP  [AFTE14P-75]  15.98 177.68 0 top
AFTP3601  AFTE14P-GP  [AFTE14P-75]  17.58 38.74 270 top
AFTP3602  AFTE14P-GP  [AFTE14P-75]  17.86 28.27 270 top
AFTP3603  AFTE14P-GP  [AFTE14P-75]  17.15 25.96 270 top
AFTP3604  AFTE14P-GP  [AFTE14P-75]  18.93 29.92 0 top
AFTP3605  AFTE14P-GP  [AFTE14P-75]  17.97 17.68 270 top
AFTP3606  AFTE14P-GP  [AFTE14P-75]  17.13 21.95 0 top
AFTP3607  AFTE14P-GP  [AFTE14P-75]  18.12 20.25 0 top
AFTP3608  AFTE14P-GP  [AFTE14P-75]  16.97 23.9 0 top
AFTP4301  AFTE14P-GP  [AFTE14P-75]  79 173.54 0 top
AFTP4302  AFTE14P-GP  [AFTE14P-75]  166.86 179.76 0 top
AFTP4303  AFTE14P-GP  [AFTE14P-75]  156.61 180.94 0 top
AFTP4304  AFTE14P-GP  [AFTE14P-75]  163.72 181.12 0 top
AFTP4305  AFTE14P-GP  [AFTE14P-75]  155.98 182.74 0 top
AFTP4306  AFTE14P-GP  [AFTE14P-75]  148.04 172.25 0 top
AFTP4307  AFTE14P-GP  [AFTE14P-75]  147.02 172.79 180 bottom
AFTP4308  AFTE14P-GP  [AFTE14P-75]  161.62 181.08 0 top
AFTP4309  AFTE14P-GP  [AFTE14P-75]  170.62 175.15 0 top
AFTP4310  AFTE14P-GP  [AFTE14P-75]  169.81 180.75 0 top
AFTP4311  AFTE14P-GP  [AFTE14P-75]  151.99 179.9 0 top
AFTP4312  AFTE14P-GP  [AFTE14P-75]  64.07 178.97 0 top
AFTP4313  AFTE14P-GP  [AFTE14P-75]  73.48 174.82 0 top
AFTP4314  AFTE14P-GP  [AFTE14P-75]  65.66 176.86 0 top
AFTP4315  AFTE14P-GP  [AFTE14P-75]  79 175.48 0 top
AFTP4601  AFTE14P-GP  [AFTE14P-75]  124.66 144.91 0 top
AFTP5602  AFTE14P-GP  [AFTE14P-75]  11.34 82.43 270 top
AFTP5603  AFTE14P-GP  [AFTE14P-75]  11.83 80.54 270 top
AFTP5604  AFTE14P-GP  [AFTE14P-75]  13.88 83.52 270 top
AFTP5605  AFTE14P-GP  [AFTE14P-75]  11.03 73.03 270 top
AFTP5606  AFTE14P-GP  [AFTE14P-75]  10.9 78.85 270 top
AFTP5607  AFTE14P-GP  [AFTE14P-75]  10.75 75.08 270 top
AFTP5608  AFTE14P-GP  [AFTE14P-75]  11.11 84.37 0 top
AFTP5609  AFTE14P-GP  [AFTE14P-75]  11.08 76.97 0 top
AFTP6001  AFTE14P-GP  [AFTE14P-75]  188.55 45.09 270 bottom
AFTP6101  AFTE14P-GP  [AFTE14P-75]  94.8 148.99 0 top
AFTP6105  AFTE14P-GP  [AFTE14P-75]  83.83 157.19 0 top
AFTP6106  AFTE14P-GP  [AFTE14P-75]  93.53 152.3 0 top
AFTP6107  AFTE14P-GP  [AFTE14P-75]  95.1 153.42 0 top
AFTP6108  AFTE14P-GP  [AFTE14P-75]  93.38 154.28 0 top
AFTP6109  AFTE14P-GP  [AFTE14P-75]  86.55 165.48 270 top
AFTP6110  AFTE14P-GP  [AFTE14P-75]  88.32 164.92 270 top
AFTP6401  AFTE14P-GP  [AFTE14P-75]  181.75 180.76 270 top
AFTP6402  AFTE14P-GP  [AFTE14P-75]  196.72 166.79 270 top
AFTP6403  AFTE14P-GP  [AFTE14P-75]  195.99 175.65 270 top
AFTP6404  AFTE14P-GP  [AFTE14P-75]  182.74 178.97 270 top
AFTP6502  AFTE14P-GP  [AFTE14P-75]  164.07 43.72 270 top
AFTP6503  AFTE14P-GP  [AFTE14P-75]  186.88 74.74 270 top
AFTP6505  AFTE14P-GP  [AFTE14P-75]  194.61 108.03 270 top
AFTP6506  AFTE14P-GP  [AFTE14P-75]  184.71 60.91 270 top
AFTP6507  AFTE14P-GP  [AFTE14P-75]  194.56 103.1 270 top
AFTP6508  AFTE14P-GP  [AFTE14P-75]  186.01 52.38 270 top
AFTP6510  AFTE14P-GP  [AFTE14P-75]  194.5 74.88 270 top
AFTP6511  AFTE14P-GP  [AFTE14P-75]  188.3 62.52 270 top
AFTP6512  AFTE14P-GP  [AFTE14P-75]  175.49 46.41 270 top
AFTP6513  AFTE14P-GP  [AFTE14P-75]  165.66 42.28 270 top
AFTP6515  AFTE14P-GP  [AFTE14P-75]  194.66 114 270 top
AFTP6516  AFTE14P-GP  [AFTE14P-75]  184.92 62.97 270 top
AFTP6517  AFTE14P-GP  [AFTE14P-75]  194.62 110.34 270 top
AFTP6518  AFTE14P-GP  [AFTE14P-75]  165.22 38.97 270 top
AFTP6519  AFTE14P-GP  [AFTE14P-75]  176.44 93.14 270 top
AFTP6520  AFTE14P-GP  [AFTE14P-75]  189.11 43.07 270 top
AFTP6521  AFTE14P-GP  [AFTE14P-75]  167.97 41.85 270 top
AFTP6522  AFTE14P-GP  [AFTE14P-75]  172.85 44.66 270 top
AFTP6523  AFTE14P-GP  [AFTE14P-75]  187.97 59.84 270 top
AFTP6524  AFTE14P-GP  [AFTE14P-75]  136.74 16.11 270 top
AFTP6525  AFTE14P-GP  [AFTE14P-75]  137.92 19.57 270 top
AFTP6526  AFTE14P-GP  [AFTE14P-75]  137.92 17.65 270 top
AFTP6527  AFTE14P-GP  [AFTE14P-75]  150.92 16.14 270 top
AFTP6528  AFTE14P-GP  [AFTE14P-75]  150.91 14.23 270 top
AFTP6529  AFTE14P-GP  [AFTE14P-75]  147.07 17.87 270 top
AFTP6530  AFTE14P-GP  [AFTE14P-75]  137.91 14.43 270 top
AFTP6531  AFTE14P-GP  [AFTE14P-75]  135.9 14.07 270 top
AFTP6532  AFTE14P-GP  [AFTE14P-75]  194.56 118.74 270 top
AFTP6533  AFTE14P-GP  [AFTE14P-75]  194.51 100.77 270 top
AFTP6534  AFTE14P-GP  [AFTE14P-75]  194.57 105.49 270 top
AFTP6535  AFTE14P-GP  [AFTE14P-75]  172.19 36.06 270 top
AFTP6536  AFTE14P-GP  [AFTE14P-75]  182.22 46.89 270 top
AFTP6537  AFTE14P-GP  [AFTE14P-75]  181.2 127.05 270 top
AFTP6538  AFTE14P-GP  [AFTE14P-75]  187.47 40.12 270 top
AFTP6539  AFTE14P-GP  [AFTE14P-75]  185.03 65.51 270 top
AFTP6540  AFTE14P-GP  [AFTE14P-75]  178.94 45.79 270 top
AFTP6601  AFTE14P-GP  [AFTE14P-75]  187.51 30.46 90 top
AFTP6602  AFTE14P-GP  [AFTE14P-75]  185.65 31.05 90 top
AFTP6603  AFTE14P-GP  [AFTE14P-75]  180 31.07 0 top
AFTP6604  AFTE14P-GP  [AFTE14P-75]  179.24 29.33 0 top
AFTP6605  AFTE14P-GP  [AFTE14P-75]  186.13 17.37 180 bottom
AFTP6606  AFTE14P-GP  [AFTE14P-75]  187.18 19.66 0 top
AFTP6607  AFTE14P-GP  [AFTE14P-75]  184.4 16.57 0 top
AFTP6608  AFTE14P-GP  [AFTE14P-75]  185.88 21.19 0 top
AFTP6609  AFTE14P-GP  [AFTE14P-75]  189.06 20.63 0 top
AFTP6610  AFTE14P-GP  [AFTE14P-75]  185.34 27 0 top
AFTP6611  AFTE14P-GP  [AFTE14P-75]  186.1 21.36 180 bottom
AFTP6612  AFTE14P-GP  [AFTE14P-75]  186.77 14.39 0 top
AFTP8902  AFTE14P-GP  [AFTE14P-75]  191.57 55.76 0 top
AFTP8903  AFTE14P-GP  [AFTE14P-75]  181.76 56.28 90 top
AFTP8904  AFTE14P-GP  [AFTE14P-75]  183.67 56.39 270 top
BATT1  ALP-CON8-17-GP-U1  [C144KA-108A7-L-1]  159.25 185.8 0 bottom
C715  SC10U6D3V3MX-GP  [C603H38]  77.24 71.99 90 bottom
C716  SC1U10V2KX-1GP  [C402H22]  130.49 95.31 90 top
C717  SC1U10V2KX-1GP  [C402H22]  127.24 95.38 270 top
C718  SCD1U16V2KX-3GP  [C402H22]  120.38 78.39 90 top
C719  SC1U10V2KX-1GP  [C402H22]  83.28 71.98 270 bottom
C720  SCD1U16V2KX-3GP  [C402H22]  127.92 91.24 0 top
C721  SCD1U16V2KX-3GP  [C402H22]  128.81 91.21 0 top
C722  SC1U10V2KX-1GP  [C402H22]  78.47 74.53 90 bottom
C1101  SC1U10V2KX-1GP  [C402H22]  117.86 101.39 0 bottom
C1102  SC1U10V2KX-1GP  [C402H22]  124.13 102.55 270 bottom
C1103  SC1U10V2KX-1GP  [C402H22]  124.13 100.92 270 bottom
C1104  SC22U6D3V3MX-1-GP  [C603H40]  157.36 78.87 90 bottom
C1106  SC22U6D3V3MX-1-GP  [C603H40]  153.12 81.56 90 top
C1108  SC22U6D3V3MX-1-GP  [C603H40]  164.07 90.27 90 bottom
C1116  SC1U10V2KX-1GP  [C402H22]  124.13 101.73 270 bottom
C1117  SC1U10V2KX-1GP  [C402H22]  118.67 101.39 0 bottom
C1136  SC1U10V2KX-1GP  [C402H22]  108.46 114.8 270 bottom
C1138  SC1U10V2KX-1GP  [C402H22]  99.55 120.09 270 top
C1147  SC1U10V2KX-1GP  [C402H22]  80.4 82.2 270 top
C1148  SC1U10V2KX-1GP  [C402H22]  103.56 86.64 0 top
C1149  SC1U10V2KX-1GP  [C402H22]  80.38 81.41 270 top
C1150  SC1U10V2KX-1GP  [C402H22]  108.45 114.01 270 bottom
C1151  SC1U10V2KX-1GP  [C402H22]  116.11 81.79 270 top
C1152  SC1U10V2KX-1GP  [C402H22]  117.63 81.76 90 top
C1153  SC1U10V2KX-1GP  [C402H22]  122.74 84.46 180 top
C1154  SC1U10V2KX-1GP  [C402H22]  123.25 81.94 90 top
C1172  SC1U10V2KX-1GP  [C402H22]  160.02 88.28 90 top
C1173  SC1U10V2KX-1GP  [C402H22]  160.02 87.51 90 top
C1174  SC1U10V2KX-1GP  [C402H22]  158.8 90.03 180 top
C1175  SC1U10V2KX-1GP  [C402H22]  157.96 90.03 180 top
C1176  SC10U6D3V3MX-GP  [C603H38]  160.14 88.85 0 bottom
C1180  SC1U10V2KX-1GP  [C402H22]  127.7 86.07 270 top
C1182  SC22U6D3V3MX-1-GP  [C603H40]  161.44 88.85 0 bottom
C1183  SC10U6D3V3MX-GP  [C603H38]  131.19 87.86 270 top
C1184  SC22U6D3V3MX-1-GP  [C603H40]  160.47 85.36 180 bottom
C1201  SC2D2U10V3KX-L-GP  [C603H36]  184.03 12.27 270 top
C1202  SC10U6D3V3MX-GP  [C603H38]  80.63 31.96 180 top
C1203  SC10U6D3V3MX-GP  [C603H38]  61.07 19.48 180 top
C1204  SC10U6D3V3MX-GP  [C603H38]  71.31 19.03 180 top
C1205  SC10U6D3V3MX-GP  [C603H38]  62.36 19.51 180 top
C1206  SC10U6D3V3MX-GP  [C603H38]  85.53 19.79 90 top
C1207  SC1U10V2KX-1GP  [C402H22]  130.43 28.91 180 top
C1208  SC10U6D3V3MX-GP  [C603H38]  69.96 19.03 180 top
C1209  SC10U6D3V3MX-GP  [C603H38]  86.27 27.33 0 top
C1210  SC10U6D3V3MX-GP  [C603H38]  81.08 19.28 0 top
C1211  SC4D7U6D3V2MX-1-GP  [C402H22]  129.6 28.96 180 top
C1212  SC4D7U6D3V2MX-1-GP  [C402H22]  133.37 27.61 0 top
C1213  SC1U10V2KX-1GP  [C402H22]  134.22 41.89 180 top
C1214  SC1U10V2KX-1GP  [C402H22]  95.28 20.04 270 top
C1215  SC1U10V2KX-1GP  [C402H22]  109.87 27.92 315 top
C1216  SC1U10V2KX-1GP  [C402H22]  94.39 39.8 180 top
C1217  SC1U10V2KX-1GP  [C402H22]  114.79 19.13 180 top
C1218  SC1U10V2KX-1GP  [C402H22]  112.08 30.13 315 top
C1219  SC1U10V2KX-1GP  [C402H22]  93.94 36.78 270 top
C1220  SC1U10V2KX-1GP  [C402H22]  128.18 40.85 0 top
C1221  SC1U10V2KX-1GP  [C402H22]  104.35 20.3 90 top
C1222  SCD022U16V2KX-3GP  [C402H22]  110.01 18.9 270 top
C1223  SC4D7U6D3V2MX-1-GP  [C402H22]  131.27 30.43 0 top
C1224  SC4D7U6D3V2MX-1-GP  [C402H22]  127.31 22.56 180 top
C1225  SC1U10V2KX-1GP  [C402H22]  128.09 22.55 180 top
C1226  SC1U10V2KX-1GP  [C402H22]  127.57 21.02 0 top
C1227  SC4D7U6D3V2MX-1-GP  [C402H22]  126.78 21.03 0 top
C1228  SCD1U16V2KX-3GP  [C402H22]  104.43 18.17 180 top
C1229  SCD1U16V2KX-3GP  [C402H22]  113.35 17.51 90 top
C1230  SC4D7U6D3V2MX-1-GP  [C402H22]  130.49 30.43 0 top
C1231  SC4D7U6D3V2MX-1-GP  [C402H22]  131.28 28.92 180 top
C1232  SC4D7U6D3V2MX-1-GP  [C402H22]  135.06 27.61 0 top
C1301  SCD1U16V2KX-3GP  [C402H22]  99.86 19.33 0 top
C1303  SC10U6D3V3MX-GP  [C603H38]  82.38 19.28 0 top
C1304  SC10U6D3V3MX-GP  [C603H38]  84.13 45.14 180 top
C1305  SC10U6D3V3MX-GP  [C603H38]  80.68 23.07 180 top
C1306  SC10U6D3V3MX-GP  [C603H38]  61.12 37.92 90 top
C1307  SC10U6D3V3MX-GP  [C603H38]  65.29 27.94 270 top
C1308  SC10U6D3V3MX-GP  [C603H38]  77.27 31.02 180 top
C1309  SC10U6D3V3MX-GP  [C603H38]  65.69 29.95 270 top
C1310  SC10U6D3V3MX-GP  [C603H38]  61.12 39.19 90 top
C1311  SC4D7U6D3V2MX-1-GP  [C402H22]  127.74 26.67 0 top
C1312  SC4D7U6D3V2MX-1-GP  [C402H22]  135 38.94 0 top
C1313  SC1U10V2KX-1GP  [C402H22]  134.16 38.94 0 top
C1314  SC1U10V2KX-1GP  [C402H22]  134.21 27.61 0 top
C1315  SC1U10V2KX-1GP  [C402H22]  60.99 40.21 90 top
C1316  SC1U10V2KX-1GP  [C402H22]  123.52 31.82 135 top
C1317  SC1U10V2KX-1GP  [C402H22]  70.52 32.23 135 top
C1318  SC1U10V2KX-1GP  [C402H22]  117.13 41.05 0 top
C1319  SC1U10V2KX-1GP  [C402H22]  120.9 29.38 135 top
C1320  SC1U10V2KX-1GP  [C402H22]  93.78 26.77 180 top
C1321  SC1U10V2KX-1GP  [C402H22]  101.02 24.51 180 top
C1322  SC1U10V2KX-1GP  [C402H22]  109.18 35.49 180 top
C1323  SCD022U16V2KX-3GP  [C402H22]  98.55 18.04 270 top
C1324  SC10U6D3V3MX-GP  [C603H38]  131.82 22 0 bottom
C1325  SC10U6D3V3MX-GP  [C603H38]  130.54 22 0 bottom
C1326  SC1U10V2KX-1GP  [C402H22]  128.35 21.03 0 top
C1327  SC1U10V2KX-1GP  [C402H22]  132.75 31.5 180 top
C1328  SCD1U16V2KX-3GP  [C402H22]  135.02 37.44 180 top
C1329  SC2D2U10V3KX-L-GP  [C603H36]  138.59 37.74 0 bottom
C1330  SC4D7U6D3V2MX-1-GP  [C402H22]  131.28 27.22 0 top
C1331  SC4D7U6D3V2MX-1-GP  [C402H22]  130.44 27.22 0 top
C1601  SCD1U16V2KX-3GP  [C402H22]  129.8 102.88 180 bottom
C1602  SCD1U16V2KX-3GP  [C402H22]  130.69 102.88 180 bottom
C1603  SCD1U16V2KX-3GP  [C402H22]  128.05 102.66 180 bottom
C1604  SCD1U16V2KX-3GP  [C402H22]  127.16 102.66 180 bottom
C1605  SCD22U10V2KX-L1-GP  [C402H22]  132.42 102.87 180 bottom
C1606  SCD22U10V2KX-L1-GP  [C402H22]  133.31 102.87 180 bottom
C1607  SCD22U10V2KX-L1-GP  [C402H22]  134.1 103.72 180 bottom
C1608  SCD22U10V2KX-L1-GP  [C402H22]  134.99 103.72 180 bottom
C1609  SCD22U10V2KX-L1-GP  [C402H22]  131.99 104.4 180 bottom
C1610  SCD22U10V2KX-L1-GP  [C402H22]  131.1 104.4 180 bottom
C1611  SCD22U10V2KX-L1-GP  [C402H22]  129.43 104.42 180 bottom
C1612  SCD22U10V2KX-L1-GP  [C402H22]  128.54 104.42 180 bottom
C1701  SC220P50V2KX-3GP  [C402H22]  157.91 75.74 270 bottom
C1704  SC10U6D3V3MX-GP  [C603H38]  161.77 85.36 180 bottom
C1801  SC15P50V2JN-2-GP  [C402H22]  119.81 103.58 90 bottom
C1802  SC15P50V2JN-2-GP  [C402H22]  121.92 103.58 270 bottom
C1803  SC3D9P50V2CN-1GP  [C402H22]  141.28 68.81 90 bottom
C1804  SC3D9P50V2CN-1GP  [C402H22]  142.79 68.81 270 bottom
C1901  SC1U10V2KX-1GP  [C402H22]  165.51 80.42 180 top
C1902  SC1U10V2KX-1GP  [C402H22]  165.06 76.88 90 top
C2101  SC1U10V2KX-1GP  [C402H22]  125.81 85.17 270 top
C2103  SC1U10V2KX-1GP  [C402H22]  139.64 82.41 270 top
C2104  SC1U10V2KX-1GP  [C402H22]  140 90.38 180 top
C2105  SC1U10V2KX-1GP  [C402H22]  131.11 86.8 270 top
C2106  SC1U10V2KX-1GP  [C402H22]  157.12 79.92 90 bottom
C2107  SC1U10V2KX-1GP  [C402H22]  131.11 85.99 270 top
C2108  SC1U10V2KX-1GP  [C402H22]  139.83 87.08 180 top
C2109  SC1U10V2KX-1GP  [C402H22]  130.99 88.94 270 top
C2110  SCD1U16V2KX-3GP  [C402H22]  131.11 85.15 270 top
C2111  SCD1U16V2KX-3GP  [C402H22]  131.11 84.33 270 top
C2112  SCD1U16V2KX-3GP  [C402H22]  143.78 64.47 0 top
C2113  SC22U6D3V3MX-1-GP  [C603H40]  156.19 94.16 180 bottom
C2114  SC22U6D3V3MX-1-GP  [C603H40]  152.1 91.41 0 top
C2116  SC1U10V2KX-1GP  [C402H22]  128.12 83.47 90 top
C2117  SC1U10V2KX-1GP  [C402H22]  167.62 79.31 180 top
C2118  SCD1U16V2KX-3GP  [C402H22]  168.42 79.31 180 top
C2119  SCD1U16V2KX-3GP  [C402H22]  167.93 79.64 0 bottom
C2120  SC1U10V2KX-1GP  [C402H22]  129.42 84.33 90 top
C2121  SC1U10V2KX-1GP  [C402H22]  140.03 92.07 0 top
C2122  SC22U6D3V3MX-1-GP  [C603H40]  156.09 96.76 90 top
C2123  SCD022U16V2KX-3GP  [C402H22]  180.22 24.05 180 bottom
C2125  SC1U10V2KX-1GP  [C402H22]  148.62 38.63 0 bottom
C2201  SC15P50V2JN-2-GP  [C402H22]  140.96 103.9 0 bottom
C2202  SC15P50V2JN-2-GP  [C402H22]  136.02 103.99 0 bottom
C2401  SC10U6D3V3MX-GP  [C603H38]  98.78 139.75 0 top
C2403  SC47P50V2JN-3GP  [C402H22]  157.31 22.42 90 bottom
C2405  SC100P50V2JN-3GP  [C402H22]  156.87 28.69 180 bottom
C2406  SCD1U16V2KX-3GP  [C402H22]  155.28 28.69 180 bottom
C2407  SCD1U16V2KX-3GP  [C402H22]  152.9 31.91 180 bottom
C2408  SCD1U16V2KX-3GP  [C402H22]  152.47 36.51 90 bottom
C2409  SCD01U50V2KX-L-GP  [C402H22]  168.09 51.54 270 bottom
C2410  SCD1U16V2KX-3GP  [C402H22]  158.8 50 0 bottom
C2411  SCD1U16V2KX-3GP  [C402H22]  168.77 48.06 90 top
C2412  SCD1U16V2KX-3GP  [C402H22]  168.77 47.24 90 top
C2413  SCD1U16V2KX-3GP  [C402H22]  154.27 33.6 180 bottom
C2414  SCD1U16V2KX-3GP  [C402H22]  171.47 32.73 90 top
C2415  SC2D2U10V3KX-L-GP  [C603H36]  148.59 34.99 270 bottom
C2416  SCD1U16V2KX-3GP  [C402H22]  148.71 33.94 270 bottom
C2417  SC2D2U10V3KX-L-GP  [C603H36]  155.32 33.58 180 bottom
C2418  SC1U10V2KX-1GP  [C402H22]  165.5 50.16 0 bottom
C2419  SCD01U50V2KX-L-GP  [C402H22]  164.29 27.13 180 bottom
C2420  SCD1U16V2KX-3GP  [C402H22]  165.33 32.34 0 top
C2421  SCD1U16V2KX-3GP  [C402H22]  148.67 33.12 270 bottom
C2422  SCD1U16V2KX-3GP  [C402H22]  155.21 39.8 180 bottom
C2423  SCD1U16V2KX-3GP  [C402H22]  177.16 37.47 270 bottom
C2424  SC18P50V2JN-1-GP  [C402H22]  153.56 42.72 270 bottom
C2425  SC18P50V2JN-1-GP  [C402H22]  153.02 38.91 90 bottom
C2426  SC2D2U10V3KX-L-GP  [C603H36]  154.87 47.87 270 bottom
C2428  SCD1U16V2KX-3GP  [C402H22]  150.19 43.99 90 top
C2429  SCD1U16V2KX-3GP  [C402H22]  171.87 42.9 270 top
C2435  SC2200P50V2KX-2GP  [C402H22]  152.45 33.85 90 bottom
C2441  SC2200P50V2KX-2GP  [C402H22]  151.48 37.17 180 top
C2501  SC10U6D3V3MX-GP  [C603H38]  145.65 56.84 90 bottom
C2502  SCD1U16V2KX-3GP  [C402H22]  145.39 55.77 90 bottom
C2503  SCD47U10V2KX-GP  [C402H22]  38.83 34.55 90 top
C2603  SC2200P50V2KX-2GP  [C402H22]  110.29 135.91 0 top
C2604  SC4D7U6D3V3KX-GP  [C603H36]  97.87 142.95 180 top
C2605  SCD1U16V2KX-3GP  [C402H22]  91.02 143.4 180 top
C2610  SCD1U16V2KX-3GP  [C402H22]  197.48 132.86 270 top
C2611  SC4D7U6D3V3KX-GP  [C603H36]  89.97 143.43 180 top
C2612  SCD1U16V2KX-3GP  [C402H22]  194.6 125.25 0 top
C2613  SC100P50V2JN-3GP  [C402H22]  193.78 125.25 0 top
C2614  SC2200P50V2KX-2GP  [C402H22]  195.8 129.4 270 bottom
C2615  SC10U6D3V3MX-GP  [C603H38]  192.91 124.61 180 bottom
C2616  SCD1U16V2KX-3GP  [C402H22]  194 124.94 180 bottom
C2617  SCD1U16V2KX-3GP  [C402H22]  188.98 120.3 90 bottom
C2618  SCD1U16V2KX-3GP  [C402H22]  189.24 117.96 90 bottom
C2702  SC2D2U10V2KX-GP  [C402H22]  175.27 14.02 180 top
C2703  SC2D2U10V2KX-GP  [C402H22]  176.07 14.02 0 top
C2704  SCD1U16V2KX-3GP  [C402H22]  167.28 12.83 0 top
C2705  SC2D2U10V2KX-GP  [C402H22]  168.07 12.83 0 top
C2706  SCD1U16V2KX-3GP  [C402H22]  178.38 15.1 270 bottom
C2707  SC10U6D3V3MX-GP  [C603H38]  178.4 14.06 270 bottom
C2708  SC2D2U10V3KX-L-GP  [C603H36]  171.36 13.63 0 bottom
C2709  SC2D2U10V2KX-GP  [C402H22]  168.86 12.83 180 top
C2710  SC10U6D3V3MX-GP  [C603H38]  166.12 15.6 180 bottom
C2711  SC10U6D3V3MX-GP  [C603H38]  167.42 15.6 180 bottom
C2713  SC10U6D3V3MX-GP  [C603H38]  164.42 22.58 0 bottom
C2714  SCD1U16V2KX-3GP  [C402H22]  170.11 20.4 90 top
C2715  SC10U6D3V3MX-GP  [C603H38]  178.3 19.6 270 bottom
C2717  SC10U6D3V3MX-GP  [C603H38]  164.82 17.34 180 bottom
C2718  SCD1U16V2KX-3GP  [C402H22]  170.11 18.8 90 top
C2720  SC10U6D3V3MX-GP  [C603H38]  165.63 24.99 0 bottom
C2721  SCD1U16V2KX-3GP  [C402H22]  166.48 24.64 180 top
C2722  SC10U6D3V3MX-GP  [C603H38]  172.3 24.77 0 bottom
C2723  SC4D7U6D3V3KX-GP  [C603H36]  174.41 24.68 0 bottom
C2725  SC10P50V2JN-L1-GP  [C402H22]  168.69 26.93 0 bottom
C2735  SCD1U16V2KX-3GP  [C402H22]  175.85 21.8 180 bottom
C2736  SCD1U16V2KX-3GP  [C402H22]  166.78 7.52 0 bottom
C2737  SCD1U16V2KX-3GP  [C402H22]  162.95 5.01 0 bottom
C2738  SCD22U10V2KX-L1-GP  [C402H22]  165.74 3.15 270 bottom
C2739  SC100P50V3JN-2GP  [C603H36]  170.77 29.87 180 bottom
C2740  SC2D2U10V2KX-GP  [C402H22]  166.92 24.99 0 bottom
C2741  SCD1U16V2KX-3GP  [C402H22]  167.27 24.64 180 top
C2902  SC10U6D3V3MX-GP  [C603H38]  181.02 16.13 90 bottom
C2907  SC10U6D3V3MX-L-GP  [C603H38]  177.96 16.26 270 bottom
C2908  SC10U6D3V3MX-L-GP  [C603H38]  177.96 17.55 270 bottom
C3102  SCD1U16V2KX-3GP  [C402H22]  53.85 170.56 90 top
C3103  SCD1U16V2KX-3GP  [C402H22]  47.63 172.49 0 bottom
C3104  SC1U10V2KX-1GP  [C402H22]  50.72 174.94 90 bottom
C3105  SC1U10V2KX-1GP  [C402H22]  60.95 178.33 0 top
C3107  SCD1U16V2KX-3GP  [C402H22]  53.85 171.45 90 top
C3108  SC4D7U6D3V3KX-GP  [C603H36]  55.81 181.43 90 top
C3109  SC4D7U6D3V3KX-GP  [C603H36]  48.7 172.19 0 bottom
C3110  SC4D7U6D3V3KX-GP  [C603H36]  54.57 176.48 90 top
C3111  SC4D7U6D3V3KX-GP  [C603H36]  46.82 176.25 180 bottom
C3112  SCD1U16V2KX-3GP  [C402H22]  44.23 175.47 270 top
C3113  SCD1U16V2KX-3GP  [C402H22]  44.81 178.13 270 top
C3114  SCD1U16V2KX-3GP  [C402H22]  50.71 174.08 90 bottom
C3115  SCD1U16V2KX-3GP  [C402H22]  46.29 173.79 270 bottom
C3116  SC15P50V2JN-2-GP  [C402H22]  47.31 178.55 270 top
C3117  SCD1U16V2KX-3GP  [C402H22]  44.65 176.93 270 top
C3118  SCD1U16V2KX-3GP  [C402H22]  52.42 177.95 90 top
C3119  SCD1U16V2KX-3GP  [C402H22]  46.29 174.63 270 bottom
C3120  SCD1U16V2KX-3GP  [C402H22]  45.06 168.7 0 top
C3121  SCD1U16V2KX-3GP  [C402H22]  62.57 180.68 90 top
C3122  SCD1U16V2KX-3GP  [C402H22]  50.71 173.23 90 bottom
C3123  SCD1U16V2KX-3GP  [C402H22]  47.88 176.13 180 bottom
C3124  SCD1U16V2KX-3GP  [C402H22]  54.49 175.44 90 top
C3125  SC15P50V2JN-2-GP  [C402H22]  49.01 178.55 270 top
C3201  SCD01U50V2KX-L-GP  [C402H22]  30.84 175.52 180 top
C3202  SC56P3KV8JN-1-GP  [C1808H40]  18.28 184.69 270 bottom
C3504  SCD1U16V2KX-3GP  [C402H22]  181.12 25.14 0 top
C3507  SCD1U16V2KX-3GP  [C402H22]  16.72 41.32 180 top
C3508  SC1U10V2KX-1GP  [C402H22]  17.55 41.32 180 top
C3510  SC1U10V2KX-1GP  [C402H22]  24.26 44.69 270 top
C3512  SC22U6D3V3MX-1-DL-GP  [C603H40]  21.07 41.45 180 top
C3513  SC22U6D3V3MX-1-DL-GP  [C603H40]  19.21 41.45 180 top
C3515  SC22U6D3V5MX-L3-GP  [C805H58]  185.36 24.57 180 bottom
C3517  SCD1U16V2KX-3GP  [C402H22]  185.76 24.67 0 top
C3518  SC1U10V2KX-1GP  [C402H22]  184.92 24.67 0 top
C3601  SCD1U16V2KX-3GP  [C402H22]  25.43 36.81 270 top
C3602  SCD1U16V2KX-3GP  [C402H22]  25.43 36.02 270 top
C3604  SCD1U16V2KX-3GP  [C402H22]  24.77 18.63 315 top
C3605  SCD1U16V2KX-3GP  [C402H22]  25.33 18.08 315 top
C3618  SCD1U16V2KX-3GP  [C402H22]  20.25 17.83 90 top
C3706  SCD1U16V2KX-3GP  [C402H22]  184.08 24.74 0 top
C4001  SC470P50V2KX-3GP  [C402H22]  44.79 38.09 0 top
C4002  SC470P50V2KX-3GP  [C402H22]  43.95 38.09 0 top
C4004  SC10U6D3V3MX-GP  [C603H38]  42.61 38.13 0 top
C4005  SC10U6D3V3MX-GP  [C603H38]  45.54 36.34 270 top
C4007  SC10U6D3V3MX-GP  [C603H38]  162.25 85.19 180 top
C4009  SC10U6D3V3MX-GP  [C603H38]  68.99 86.39 180 top
C4012  SC10U6D3V3MX-GP  [C603H38]  159.85 89.87 0 top
C4013  SC10U6D3V3MX-GP  [C603H38]  164.44 87.96 270 top
C4016  SC10U6D3V3MX-GP  [C603H38]  164.41 86.08 270 top
C4017  SCD1U16V2KX-3GP  [C402H22]  166.3 80.42 0 top
C4018  SCD1U16V2KX-3GP  [C402H22]  170.36 91.83 90 top
C4028  SC1U10V2KX-1GP  [C402H22]  170.16 90.23 90 top
C4029  SC1U10V2KX-1GP  [C402H22]  170.16 89.43 90 top
C5501  SCD1U16V2KX-3GP  [C402H22]  110.24 172.29 90 bottom
C5505  SC4D7U6D3V3KX-GP  [C603H36]  98.21 182.1 270 top
C5506  SC22U6D3V3MX-1-GP  [C603H40]  98.5 176.63 90 top
C5508  SCD1U16V2KX-3GP  [C402H22]  101.61 170.82 0 bottom
C5515  SC1KP50V2KX-L-1-GP  [C402H22]  93.28 176.23 270 top
C5531  SCD1U16V2KX-3GP  [C402H22]  98.54 170.69 0 bottom
C5532  SCD1U16V2KX-3GP  [C402H22]  102.41 170.81 0 bottom
C5533  SCD1U16V2KX-3GP  [C402H22]  99.35 170.69 0 bottom
C5534  SCD1U16V2KX-3GP  [C402H22]  103.26 170.79 0 bottom
C5535  SCD1U50V3KX-GP  [C603H36]  93.17 177.29 270 top
C5536  SC1U10V2KX-1GP  [C402H22]  98.2 175.59 90 top
C5537  SCD1U16V2KX-3GP  [C402H22]  104.05 170.79 0 bottom
C5538  SC10U6D3V3MX-GP  [C603H38]  98.6 174.56 90 top
C5539  SC4D7U6D3V3KX-GP  [C603H36]  111.19 177.98 90 top
C5540  SC10P50V2JN-L1-GP  [C402H22]  109.84 170.66 180 bottom
C5541  SC10P50V2JN-L1-GP  [C402H22]  108.55 171.08 90 bottom
C5543  SC2D2U10V3KX-L-GP  [C603H36]  113.58 177.97 270 top
C5601  SCD1U16V2KX-3GP  [C402H22]  30.41 77.2 270 top
C5602  SCD1U16V2KX-3GP  [C402H22]  20.47 79.06 270 top
C5603  SCD1U16V2KX-3GP  [C402H22]  28.68 78.82 270 top
C5604  SCD1U16V2KX-3GP  [C402H22]  28.68 79.63 270 top
C5605  SCD1U16V2KX-3GP  [C402H22]  30.41 78.09 270 top
C5606  SCD1U16V2KX-3GP  [C402H22]  26.94 73.52 270 bottom
C5607  SC100P50V2JN-3GP  [C402H22]  11.89 84 0 bottom
C5608  SC2D2U10V3KX-L-GP  [C603H36]  23.68 71.6 180 bottom
C5609  SCD1U16V2KX-3GP  [C402H22]  22.63 71.76 180 bottom
C5610  SCD1U16V2KX-3GP  [C402H22]  22.55 74.16 0 bottom
C5611  SC15P50V2JN-2-GP  [C402H22]  16.24 75.25 0 top
C5612  SC15P50V2JN-2-GP  [C402H22]  16.67 72.68 0 top
C5613  SC15P50V2JN-2-GP  [C402H22]  16.31 78.3 0 top
C5614  SC15P50V2JN-2-GP  [C402H22]  12.99 75.25 0 top
C5615  SC10U6D3V3MX-GP  [C603H38]  19.37 76.3 90 bottom
C5616  SC18P50V2JN-1-GP  [C402H22]  11.9 80.19 180 bottom
C5617  SC18P50V2JN-1-GP  [C402H22]  11.87 78.42 180 bottom
C5618  SC15P50V2JN-2-GP  [C402H22]  13.13 78.58 0 top
C5619  SC15P50V2JN-2-GP  [C402H22]  13.43 72.84 0 top
C5620  SCD1U16V2KX-3GP  [C402H22]  28.68 76.08 90 top
C5621  SC10U6D3V3MX-GP  [C603H38]  27.29 72.47 90 bottom
C5622  SC100P50V2JN-3GP  [C402H22]  11.89 82.45 180 bottom
C5623  SCD01U16V2KX-3GP  [C402H22]  15.43 82.43 180 top
C5624  SCD1U16V2KX-3GP  [C402H22]  28.68 74.37 270 top
C5625  SCD1U16V2KX-3GP  [C402H22]  28.68 75.19 270 top
C5626  SCD1U16V2KX-3GP  [C402H22]  27.84 82.15 90 bottom
C5627  SCD1U16V2KX-3GP  [C402H22]  19.31 77.35 90 bottom
C5628  SC10U6D3V3MX-GP  [C603H38]  19.18 77.11 270 top
C5629  SC4D7P50V2BN-GP  [C402H22]  20.45 79.89 270 top
C5701  SCD1U16V2KX-3GP  [C402H22]  22.15 51.09 270 top
C5702  SCD1U16V2KX-3GP  [C402H22]  16.9 58.47 90 top
C5703  SCD1U16V2KX-3GP  [C402H22]  22.15 51.93 270 top
C5704  SCD1U16V2KX-3GP  [C402H22]  22.15 50.25 270 top
C5705  SCD1U16V2KX-3GP  [C402H22]  22.15 52.76 270 top
C5706  SCD1U16V2KX-3GP  [C402H22]  21.57 46.99 270 top
C5707  SCD1U16V2KX-3GP  [C402H22]  21.57 47.8 270 top
C5708  SCD1U16V2KX-3GP  [C402H22]  21.57 45.9 270 top
C5709  SCD1U16V2KX-3GP  [C402H22]  21.57 45.09 270 top
C6001  SCD1U16V2KX-3GP  [C402H22]  186.34 47.02 90 bottom
C6002  SC10U6D3V3MX-GP  [C603H38]  186.24 48.41 90 bottom
C6003  SCD22U10V2KX-L1-GP  [C402H22]  185.02 42.27 270 bottom
C6004  SCD22U10V2KX-L1-GP  [C402H22]  185.02 41.38 270 bottom
C6005  SCD22U10V2KX-L1-GP  [C402H22]  185.02 39.6 270 bottom
C6006  SCD22U10V2KX-L1-GP  [C402H22]  185.02 40.49 270 bottom
C6007  SCD1U16V2KX-3GP  [C402H22]  186.45 44.33 90 bottom
C6008  SC10U6D3V3MX-GP  [C603H38]  186.27 45.65 90 bottom
C6009  SC10U6D3V3MX-GP  [C603H38]  183.98 87.89 90 bottom
C6010  SCD01U50V2KX-L-GP  [C402H22]  182.18 81.68 90 top
C6011  SCD01U50V2KX-L-GP  [C402H22]  182.18 82.5 90 top
C6013  SCD01U50V2KX-L-GP  [C402H22]  182.18 80.87 90 top
C6014  SCD01U50V2KX-L-GP  [C402H22]  182.18 80.05 90 top
C6018  SCD1U16V2KX-3GP  [C402H22]  183.12 85.24 180 top
C6101  SCD1U16V2KX-3GP  [C402H22]  87.89 170.5 90 bottom
C6102  SCD1U16V2KX-3GP  [C402H22]  87.89 169.68 90 bottom
C6103  SCD1U16V2KX-3GP  [C402H22]  96.11 147.25 0 top
C6104  SCD1U16V2KX-3GP  [C402H22]  93.85 171.08 0 bottom
C6105  SC10U6D3V3MX-GP  [C603H38]  88 171.55 90 bottom
C6106  SC10U6D3V3MX-GP  [C603H38]  92.77 171.07 0 bottom
C6316  SCD1U16V2KX-3GP  [C402H22]  185 66.23 270 bottom
